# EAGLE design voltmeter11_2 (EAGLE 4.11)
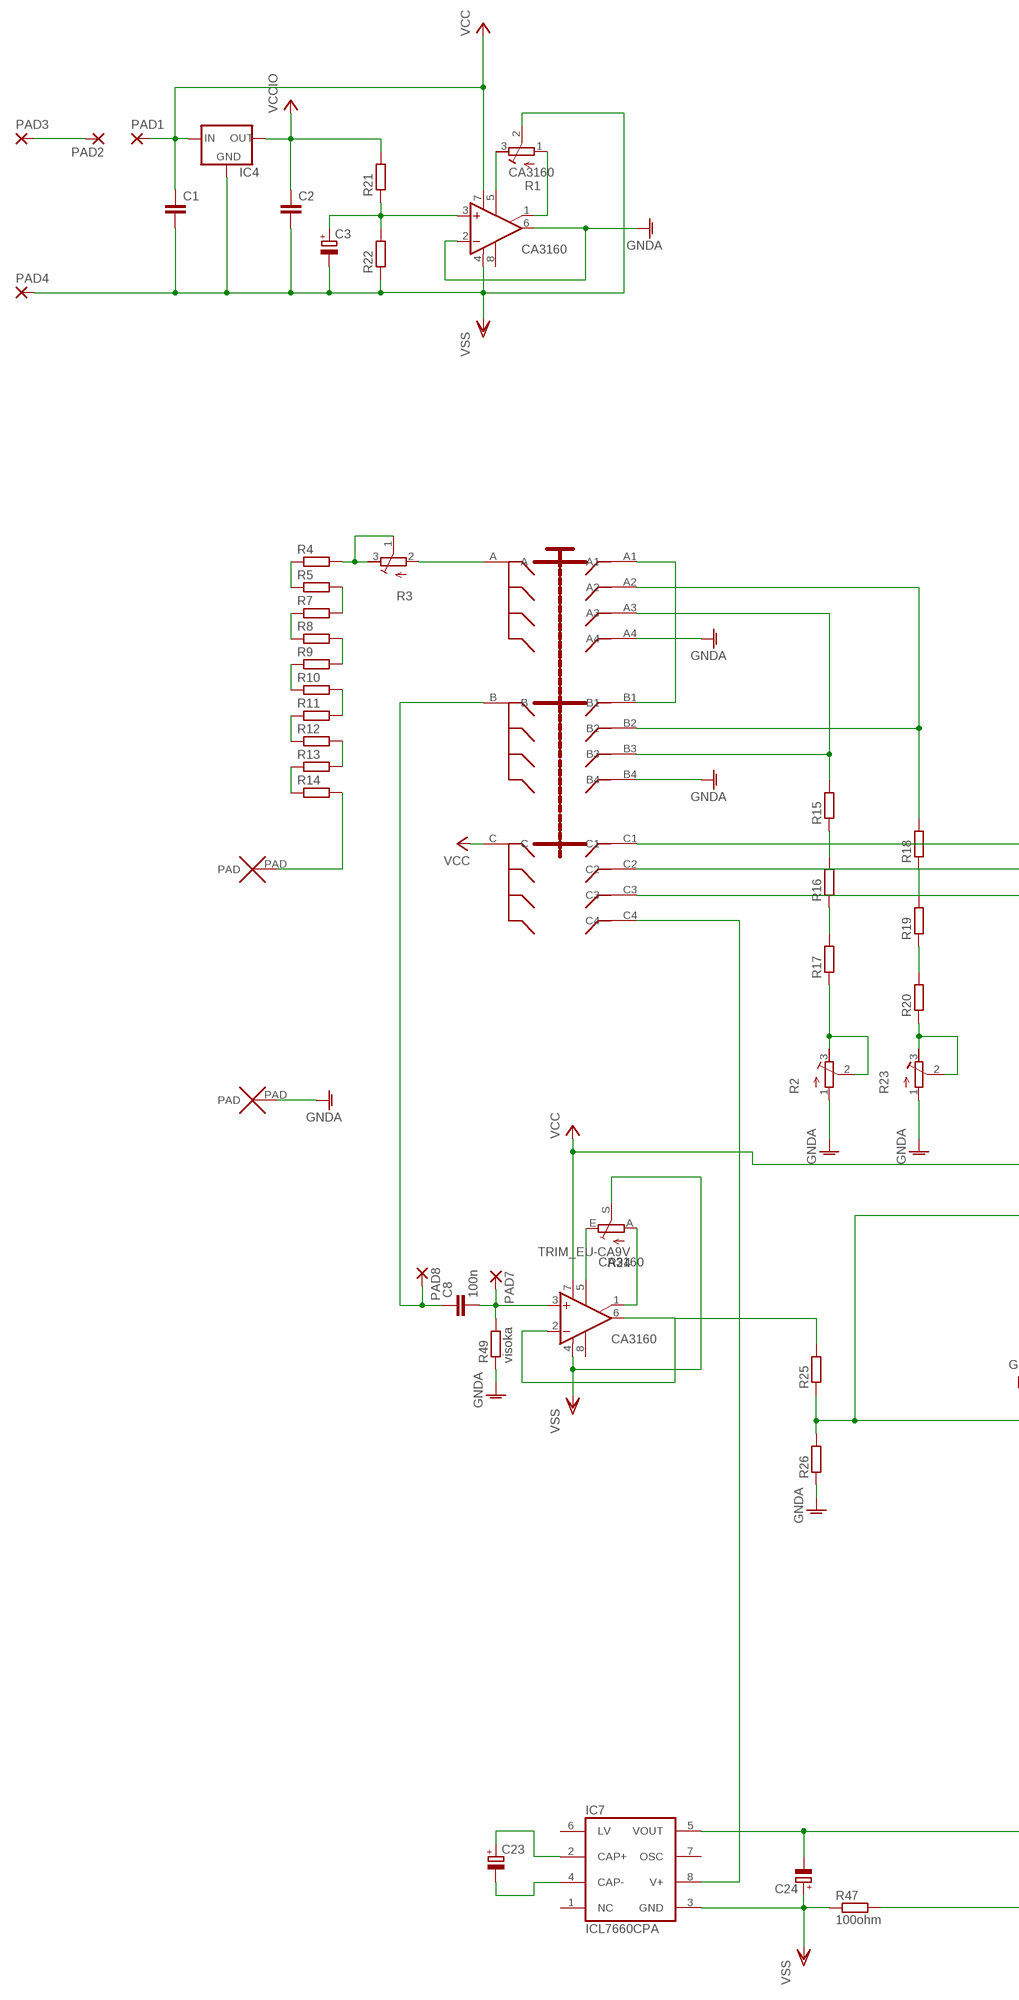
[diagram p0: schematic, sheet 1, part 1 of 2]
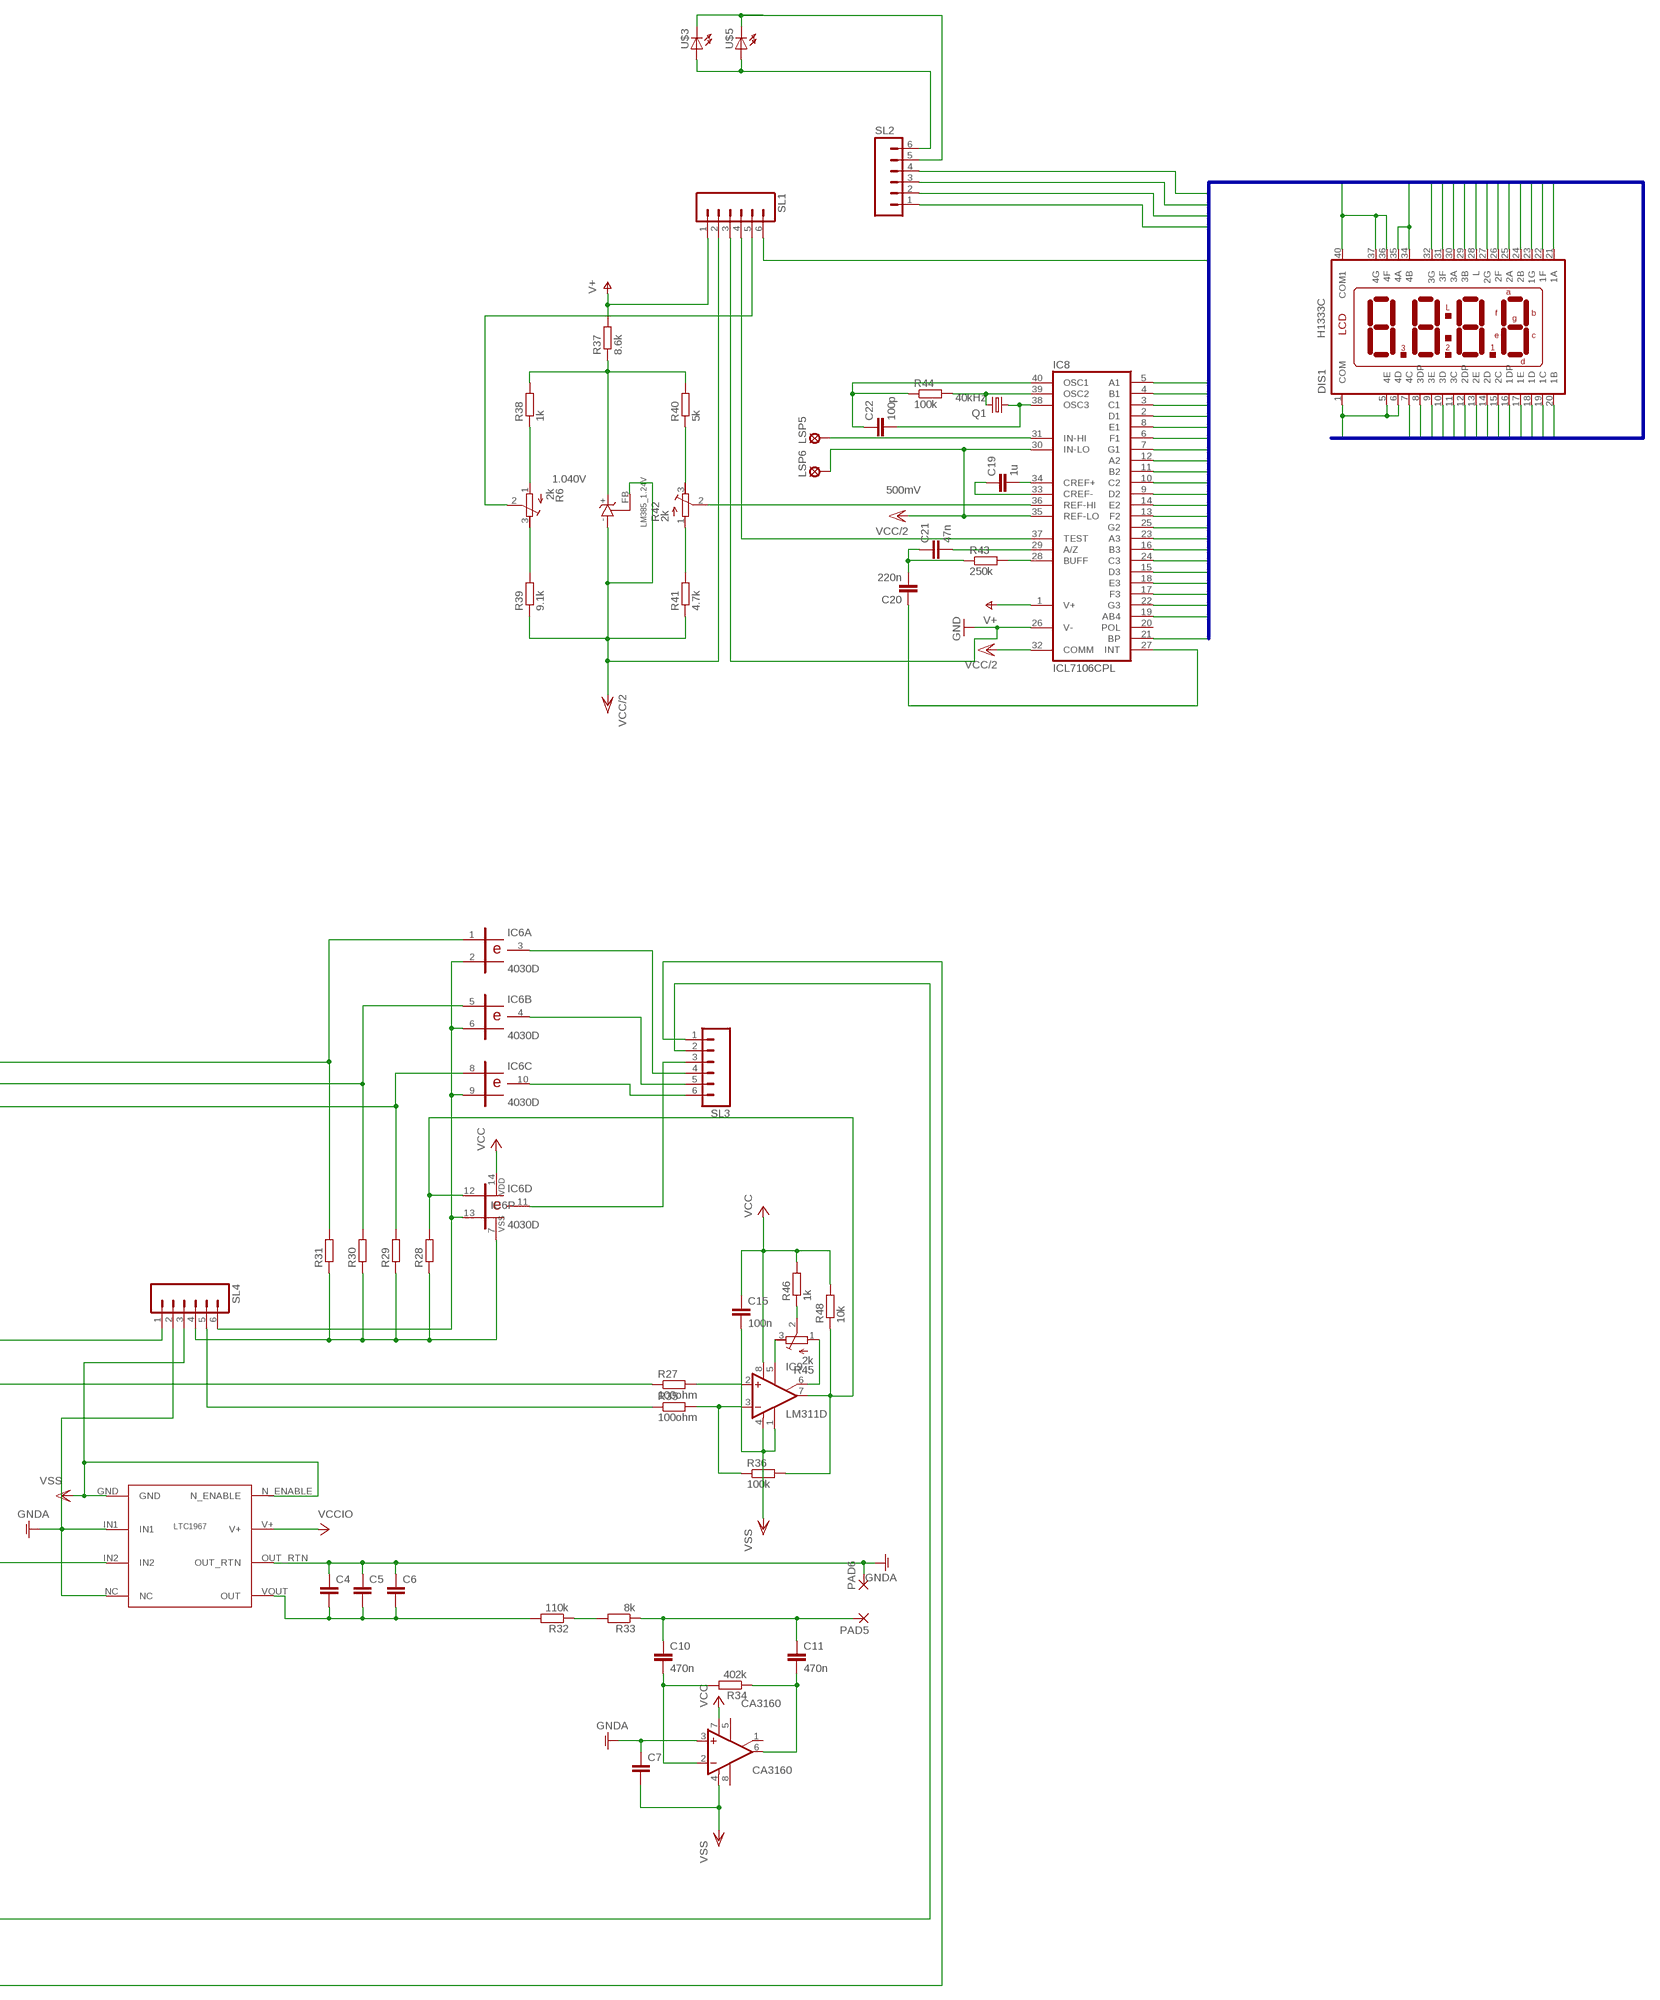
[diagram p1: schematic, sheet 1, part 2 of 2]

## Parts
C1  C-EUC1206  [C1206]
C2  C-EUC1206  [C1206]
C3  CPOL-EUB  [PANASONIC_B]
C4  C-EU050-050X075  [C050-050X075]
C5  C-EU050-050X075  [C050-050X075]
C6  C-EU050-035X075  [C050-035X075]
C7  C-EUC1206  [C1206]
C8  100n  C-EUC1206  [C1206]
C10  470n  C-EUC1206  [C1206]
C11  470n  C-EUC1206  [C1206]
C15  100n  C-EUC1206  [C1206]
C19  1u  C-EU050-050X075  [C050-050X075]
C20  220n  C-EU050-024X044  [C050-024X044]
C21  47n  C-EU050-024X044  [C050-024X044]
C22  100p  C-EUC1206  [C1206]
C23  CPOL-EUE5-8.5  [E5-8,5]
C24  CPOL-EUE5-8.5  [E5-8,5]
D2  LM385_1.24V  [LM385_1.24V]
DIS1  H1333C  [H1333C]
IC1  LTC1967  [LTC1967]
IC2  CA3160  [CA3160]
IC3  CA3160  [CA3160]
IC4  78XXL  [78XXL]
IC5  CA3160  [CA3160]
IC6  4030D  [SO14]
IC7  ICL7660CPA  [DIL08]
IC8  ICL7106CPL  [DIL40]
IC9  LM311D  [SO08]
LSP5  LSP10  [LSP10]
LSP6  LSP10  [LSP10]
PAD1  1,6/0,8  [1,6/0,8]
PAD2  1,6/0,8  [1,6/0,8]
PAD3  1,6/0,8  [1,6/0,8]
PAD4  1,6/0,8  [1,6/0,8]
PAD5  1,6/0,8  [1,6/0,8]
PAD6  1,6/0,8  [1,6/0,8]
PAD7  1,6/0,8  [1,6/0,8]
PAD8  1,6/0,8  [1,6/0,8]
Q1  40kHz  CRYTALTC26V  [TC26V]
R1  TRIMER  [C3203]
R2  TRIMER  [C3203]
R3  TRIMER406  [406]
R4  R-EU_R1206  [R1206]
R5  R-EU_R1206  [R1206]
R6  2k  TRIMER  [C3203]
R7  R-EU_R1206  [R1206]
R8  R-EU_R1206  [R1206]
R9  R-EU_R1206  [R1206]
R10  R-EU_R1206  [R1206]
R11  R-EU_R1206  [R1206]
R12  R-EU_R1206  [R1206]
R13  R-EU_R1206  [R1206]
R14  R-EU_R1206  [R1206]
R15  R-EU_R1206  [R1206]
R16  R-EU_R1206  [R1206]
R17  R-EU_R1206  [R1206]
R18  R-EU_R1206  [R1206]
R19  R-EU_R1206  [R1206]
R20  R-EU_R1206  [R1206]
R21  R-EU_R1206  [R1206]
R22  R-EU_R1206  [R1206]
R23  TRIMER  [C3203]
R24  TRIM_EU-CA9V  [CA9V]
R25  R-EU_R1206  [R1206]
R26  R-EU_R1206  [R1206]
R27  100ohm  R-EU_R1206  [R1206]
R28  R-EU_R1206  [R1206]
R29  R-EU_R1206  [R1206]
R30  R-EU_R1206  [R1206]
R31  R-EU_R1206  [R1206]
R32  110k  R-EU_R1206  [R1206]
R33  8k  R-EU_R1206  [R1206]
R34  402k  R-EU_R1206  [R1206]
R35  100ohm  R-EU_R1206  [R1206]
R36  100k  R-EU_R1206  [R1206]
R37  8.6k  R-EU_R1206  [R1206]
R38  1k  R-EU_R1206  [R1206]
R39  9.1k  R-EU_R1206  [R1206]
R40  5k  R-EU_R1206  [R1206]
R41  4.7k  R-EU_R1206  [R1206]
R42  2k  TRIMER  [C3203]
R43  250k  R-EU_R1206  [R1206]
R44  100k  R-EU_R1206  [R1206]
R45  2k  TRIMER  [C3203]
R46  1k  R-EU_R1206  [R1206]
R47  100ohm  R-EU_R1206  [R1206]
R48  10k  R-EU_R1206  [R1206]
R49  visoka  R-EU_R1206  [R1206]
S1  PREKLOPNIK_3NA4_HTE  [PREKLOPNIK_3NA4_HTE]
SL1  M06  [06P]
SL2  M06  [06P]
SL3  M06  [06P]
SL4  M06  [06P]
U$1  PAD  [PUSA]
U$2  PAD  [PUSA]
U$3  LEDB155  [Q62902-B155]
U$5  LEDB155  [Q62902-B155]

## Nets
1.040V: R6.2 SL1.5
1.040V1: R35.1 SL4.5
1DP: DIS1.16(1DP) SL2.1
2DP: DIS1.12(2DP) SL2.2
2V_: IC6.3(A:O) SL3.4
2VXOR: IC6.1(A:I0) R31.2 S1.C1
3DP: DIS1.8(3DP) SL2.3
20V: R18.2 S1.A2 S1.B2
20V_: IC6.4(B:O) SL3.5
20VXOR: IC6.5(B:I0) R30.2 S1.C2
200V: R15.2 S1.A3 S1.B3
200V_: IC6.10(C:O) SL3.6
200VXOR: IC6.8(C:I0) R29.2 S1.C3
A1: DIS1.21(1A) IC8.5(A1)
A2: DIS1.25(2A) IC8.12(A2)
A3: DIS1.30(3A) IC8.23(A3)
AB4: DIS1.7(4C) DIS1.34(4B) DIS1.35(4A) IC8.19(AB4)
B1: DIS1.20(1B) IC8.4(B1)
B2: DIS1.24(2B) IC8.11(B2)
B3: DIS1.29(3B) IC8.16(B3)
BP: DIS1.1(COM) DIS1.5(4E) DIS1.6(4D) DIS1.36(4F) DIS1.37(4G) DIS1.40(COM1) IC8.21(BP) SL1.6
BPXOR: IC6.2(A:I1) IC6.6(B:I1) IC6.9(C:I1) IC6.13(D:I1) SL4.6
C1: DIS1.19(1C) IC8.3(C1)
C2: DIS1.15(2C) IC8.10(C2)
C3: DIS1.11(3C) IC8.24(C3)
CLIP: DIS1.28(L) SL2.4
CLIP1: IC6.12(D:I0) IC9.7(OUT) R28.2 R36.2 R48.1
CLIP_: IC6.11(D:O) SL3.3
D1: DIS1.18(1D) IC8.2(D1)
D2: DIS1.14(2D) IC8.9(D2)
D3: DIS1.10(3D) IC8.15(D3)
DIG_GND: IC8.37(TEST) SL1.4
DIGGND: IC6.7(P:VSS) R28.1 R29.1 R30.1 R31.1 SL4.4
E1: DIS1.17(1E) IC8.8(E1)
E2: DIS1.13(2E) IC8.14(E2)
E3: DIS1.9(3E) IC8.18(E3)
F1: DIS1.22(1F) IC8.6(F1)
F2: DIS1.26(2F) IC8.13(F2)
F3: DIS1.31(3F) IC8.17(F3)
G1: DIS1.23(1G) IC8.7(G1)
G2: DIS1.27(2G) IC8.25(G2)
G3: DIS1.32(3G) IC8.22(G3)
GND: IC8.26(V-) SL1.3
GNDA: C4.1 C5.1 C6.1 C7.1 IC1.IN1 IC1.NC IC1.OUT_RTN IC2.2(-IN) IC2.6(OUT) IC5.3(+IN) PAD6.1(P) R2.1 R23.1 R26.1 R49.1 S1.A4 S1.B4 SL4.2 U$2.PAD
LED+: SL2.6 U$3.A U$5.A
LED+1: R47.2 SL3.1
LED-: SL2.5 U$3.K(C) U$5.K(C)
LED-1: C24.- IC7.5(VOUT) SL3.2
N$3: R3.2 S1.A
N$4: R4.1 R5.1
N$5: R5.2 R7.2
N$6: R7.1 R8.1
N$7: R8.2 R9.2
N$8: R9.1 R10.1
N$9: C19.2 IC8.34(CREF+)
N$10: R10.2 R11.2
N$11: R11.1 R12.1
N$12: R12.2 R13.2
N$13: R13.1 R14.1
N$14: R14.2 U$1.PAD
N$15: S1.A1 S1.B1
N$16: C3.+ IC2.3(+IN) R21.1 R22.2
N$17: IC1.IN2 R25.1 R26.2 R27.1
N$18: C8.1 PAD8.1(P) S1.B
N$19: C23.+ IC7.2(CAP+)
N$20: R3.1 R3.3 R4.2
N$21: PAD2.1(P) PAD3.1(P)
N$22: R15.1 R16.2
N$23: R18.1 R19.2
N$24: R16.1 R17.2
N$25: R19.1 R20.2
N$26: R2.2 R2.3 R17.1
N$27: IC3.2(-IN) IC3.6(OUT) R25.2
N$28: R20.1 R23.2 R23.3
N$29: IC2.5(OFFSET2) R1.3
N$30: IC2.1(OFFSET1) R1.1
N$31: IC3.5(OFFSET2) R24.E
N$32: IC3.1(OFFSET1) R24.A
N$33: C8.2 IC3.3(+IN) PAD7.1(P) R49.2
N$34: IC9.3(-IN) R35.2 R36.1
N$35: C23.- IC7.4(CAP-)
N$36: R32.1 R33.2
N$37: C10.1 C11.1 PAD5.1(P) R33.1
N$39: C4.2 C5.2 C6.2 IC1.VOUT(OUT) R32.2
N$40: IC9.2(+IN) R27.2
N$41: C10.2 IC5.2(-IN) R34.2
N$42: C11.2 IC5.6(OUT) R34.1
N$48: IC9.5(ON) R45.3
N$49: IC9.6(ON/STR) R45.1
N$50: R45.2 R46.1
N$58: D2.+ R37.1 R38.2 R40.2
N$59: IC8.36(REF-HI) R42.2
N$60: R6.1 R38.1
N$61: R40.1 R42.3
N$62: R6.3 R39.2
N$63: R41.2 R42.1
N$64: C19.1 IC8.33(CREF-)
N$65: IC8.31(IN-HI) LSP5.MP
N$67: C21.2 IC8.29(A/Z)
N$68: IC8.28(BUFF) R43.2
N$70: C20.2 C21.1 R43.1
N$71: C20.1 IC8.27(INT)
N$72: C22.2 IC8.38(OSC3) Q1.1
N$73: C22.1 IC8.40(OSC1) R44.1
N$75: IC8.39(OSC2) Q1.2 R44.2
N$84: IC7.8(V+) S1.C4
VBATT: IC8.1(V+) R37.2 SL1.1 ; supply symbol labelled V+
VCC: C1.1 C15.1 IC2.7(+V) IC3.7(+V) IC4.IN IC5.7(+V) IC6.14(P:VDD) IC9.8(V+) PAD1.1(P) R46.2 R48.2 S1.C SL4.1
VCC/2_+_50MV: D2.- D2.FB IC8.30(IN-LO) IC8.32(COMM) IC8.35(REF-LO) LSP6.MP R39.1 R41.1 SL1.2 ; supply symbol labelled VCC/2
VCCIO: C2.1 IC1.V+ IC4.OUT R21.2
VSS: C1.2 C2.2 C3.- C7.2 C15.2 C24.+ IC1.GND IC1.N_ENABLE IC2.4(V-) IC3.4(V-) IC4.GND IC5.4(V-) IC7.3(GND) IC9.1(GND) IC9.4(V-) PAD4.1(P) R1.2 R22.1 R24.S R47.1 SL4.3
Unconnected: IC2.8(STROBE) IC3.8(STROBE) IC5.1(OFFSET1) IC5.5(OFFSET2) IC5.8(STROBE) IC7.1(NC) IC7.6(LV) IC7.7(OSC) IC8.20(POL)

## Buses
B$1

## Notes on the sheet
- 1.040V
- 500mV

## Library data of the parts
C1 C2 C4-C8 C10 C11 C15 C19-C22 = rcl:C-EU: CAPACITOR, European symbol
C3 C23 C24 = rcl:CPOL-EU: POLARIZED CAPACITOR, European symbol
D2 = voltmeter:LM385_1.24V
DIS1 = display-lcd:H1333C: LCD DISPLAY 4-character 7 segment
IC1 = voltmeter:LTC1967
IC2 IC3 IC5 = voltmeter:CA3160
IC4 = v-reg:78XXL: VOLTAGE REGULATOR
IC6 = 40xx:4030: Quad XOR
IC7 = maxim:ICL7660CPA: VOLTAGE CONVERTER
IC8 = maxim:ICL7106CPL: LCD DRIVER
IC9 = linear:LM311: COMPARATOR
LSP5 LSP6 = solpad:LSP10: SOLDER PAD
PAD1-PAD8 = wirepad:1,6/0,8: THROUGH-HOLE PAD
Q1 = crystal:CRYTAL: CRYSTAL
R1-R3 R6 R23 R42 R45 = voltmeter:TRIMER
R4 R5 R7-R22 R25-R41 R43 R44 R46-R49 = rcl:R-EU_: RESISTOR, European symbol
R24 = pot:TRIM_EU-: POTENTIOMETER
S1 = voltmeter:PREKLOPNIK_3NA4_HTE
SL1-SL4 = con-amp-quick:M06: AMP QUICK CONNECTOR
U$1 U$2 = voltmeter:PAD
U$3 U$5 = led:LED: LED

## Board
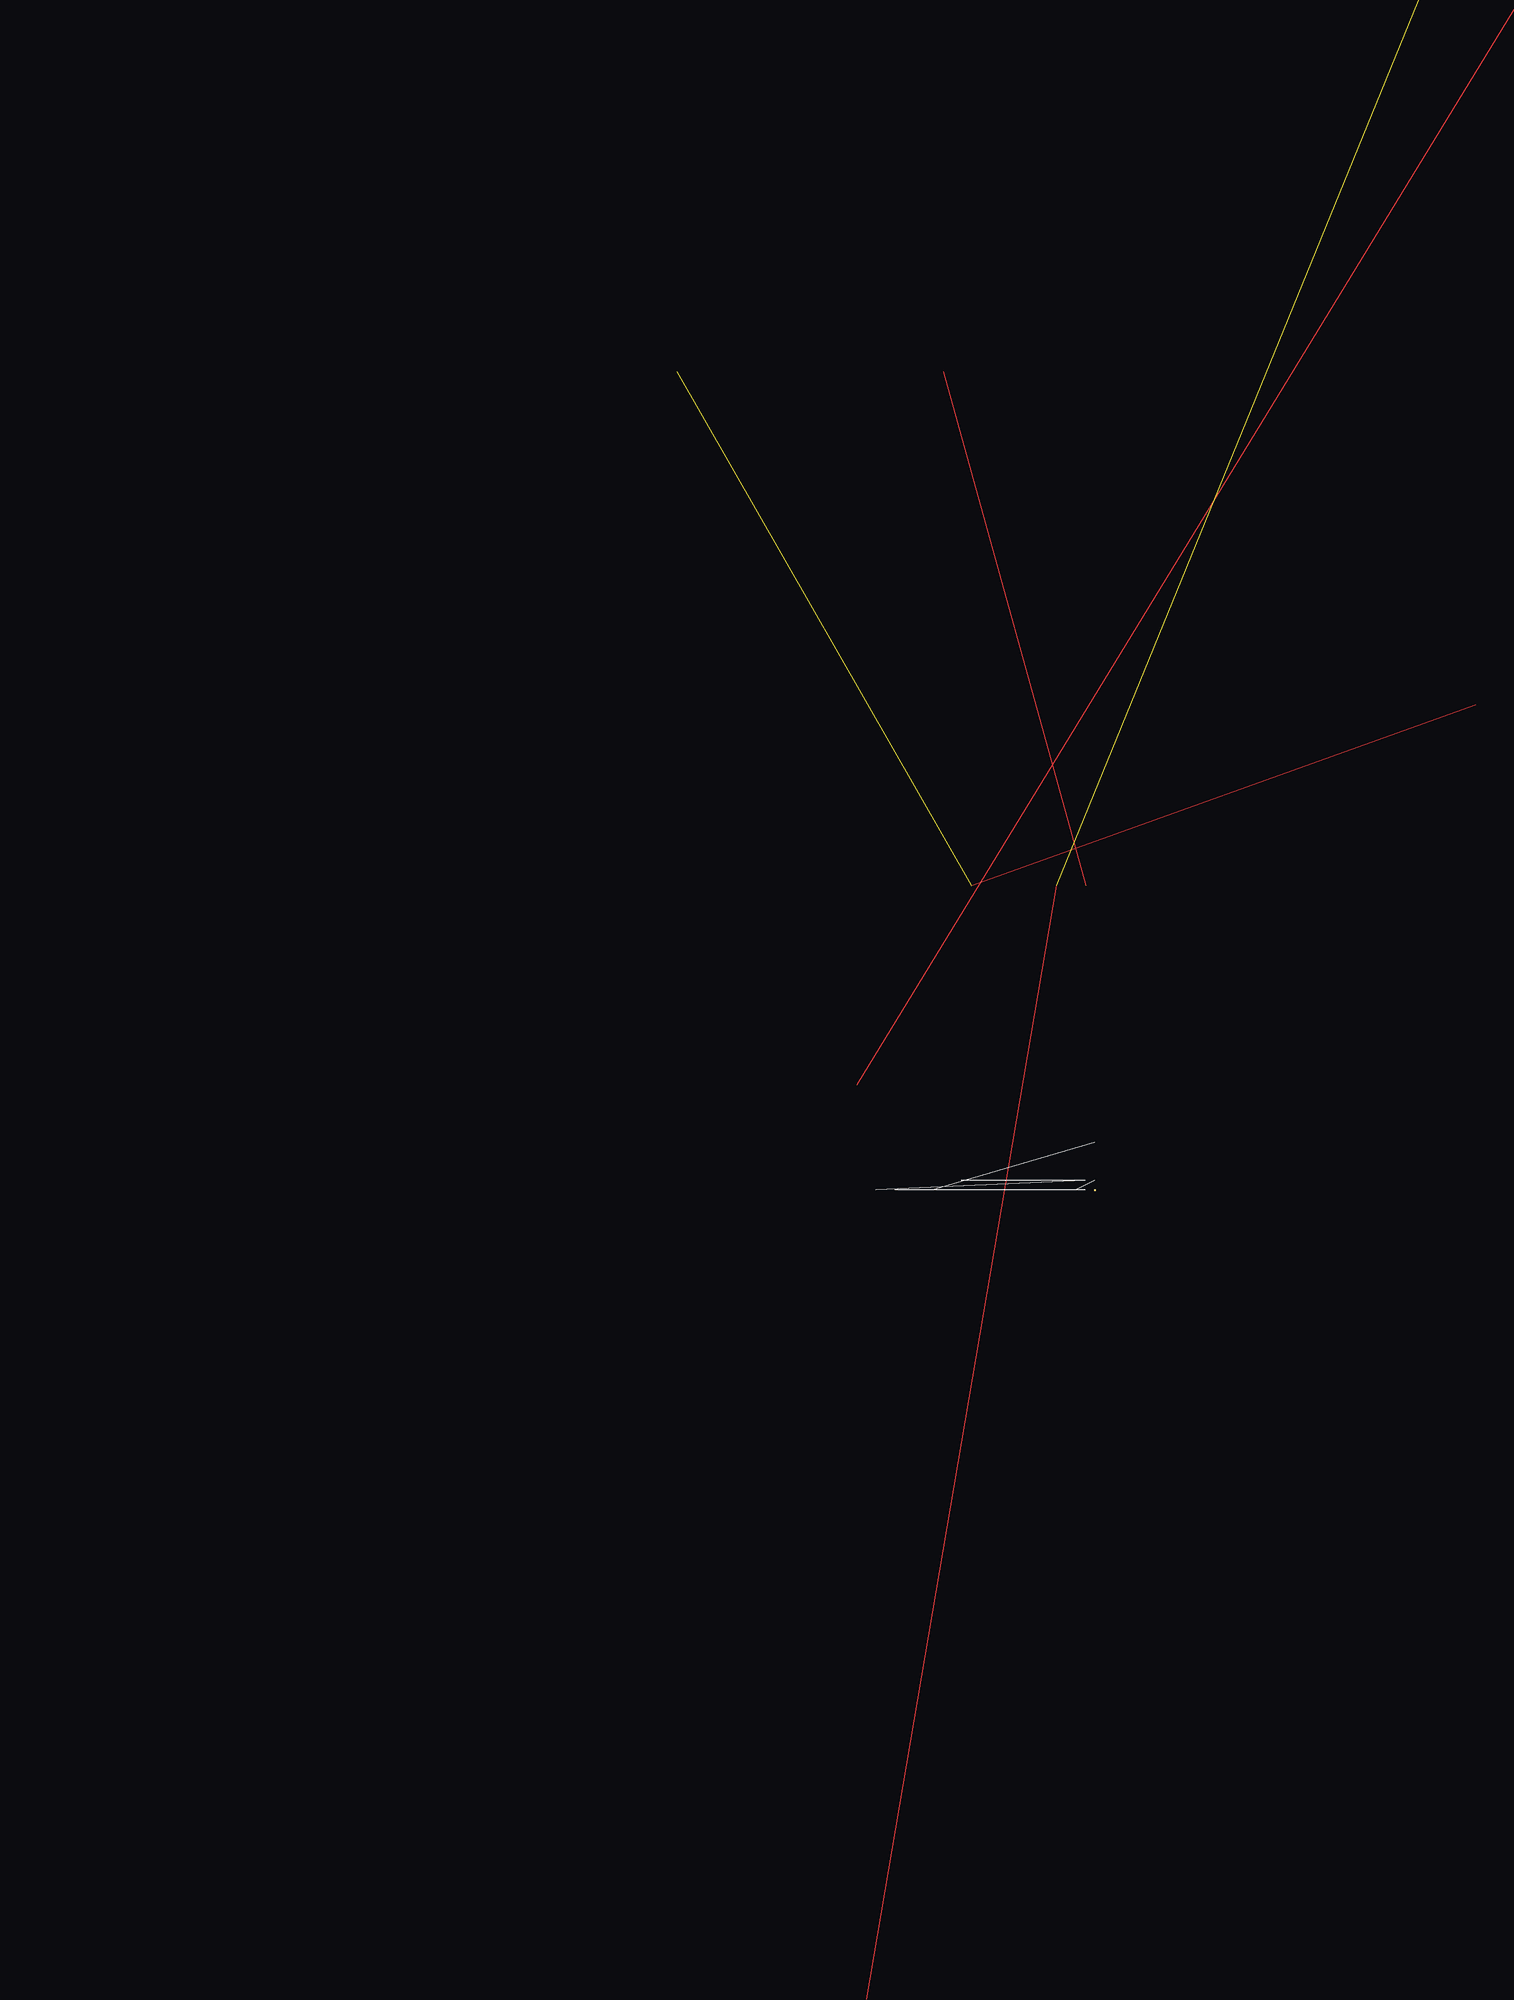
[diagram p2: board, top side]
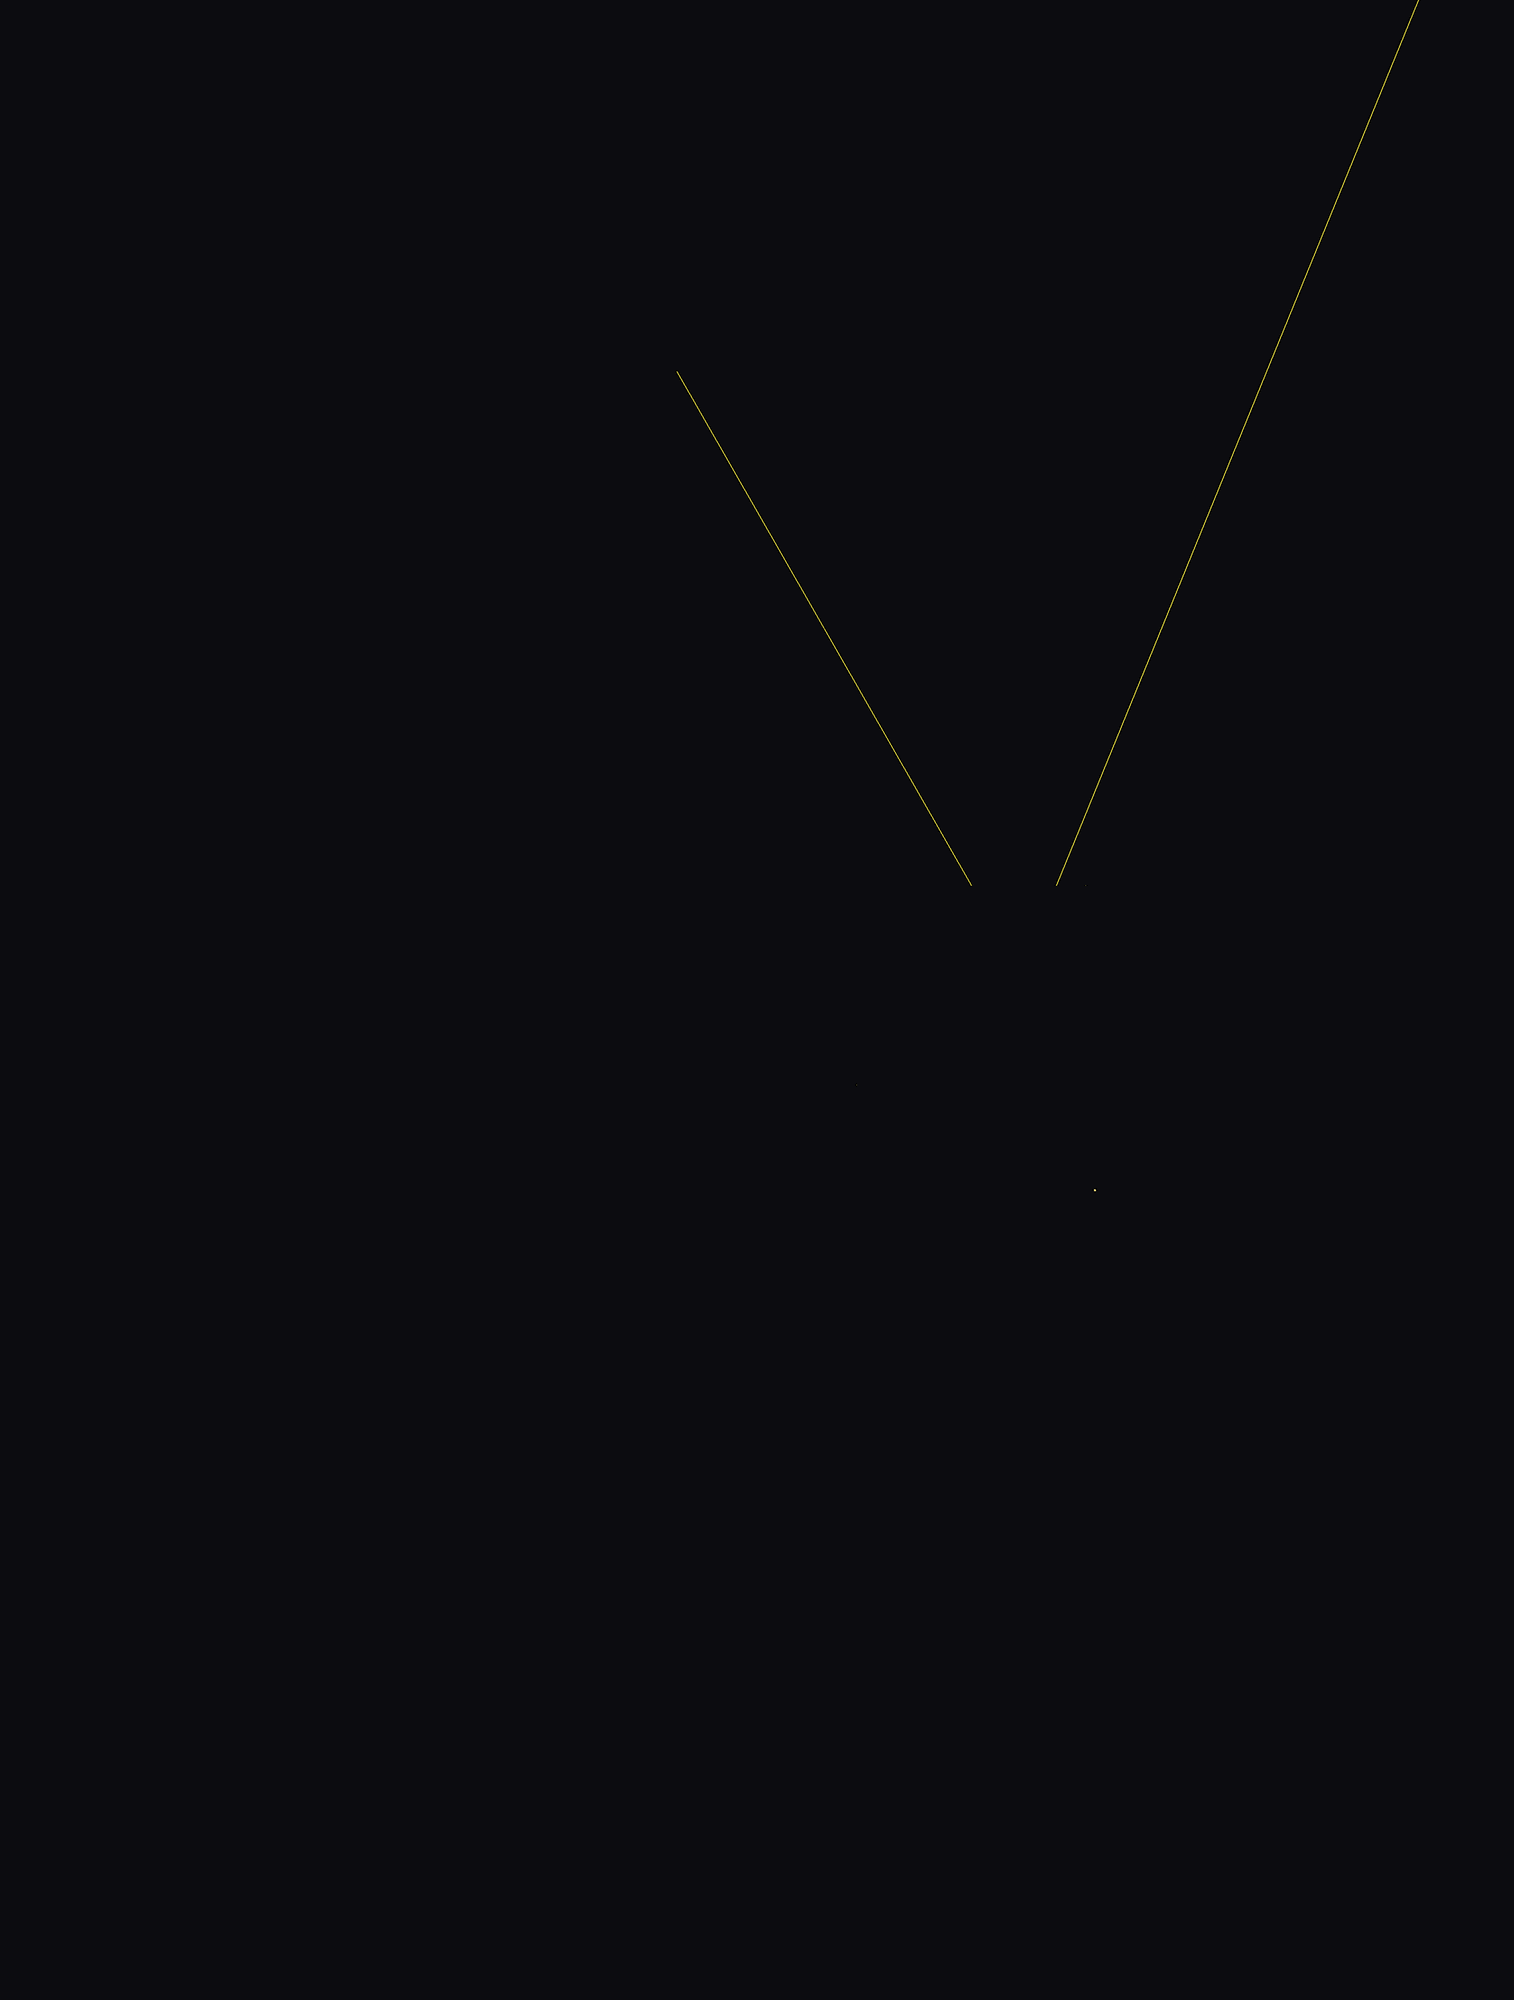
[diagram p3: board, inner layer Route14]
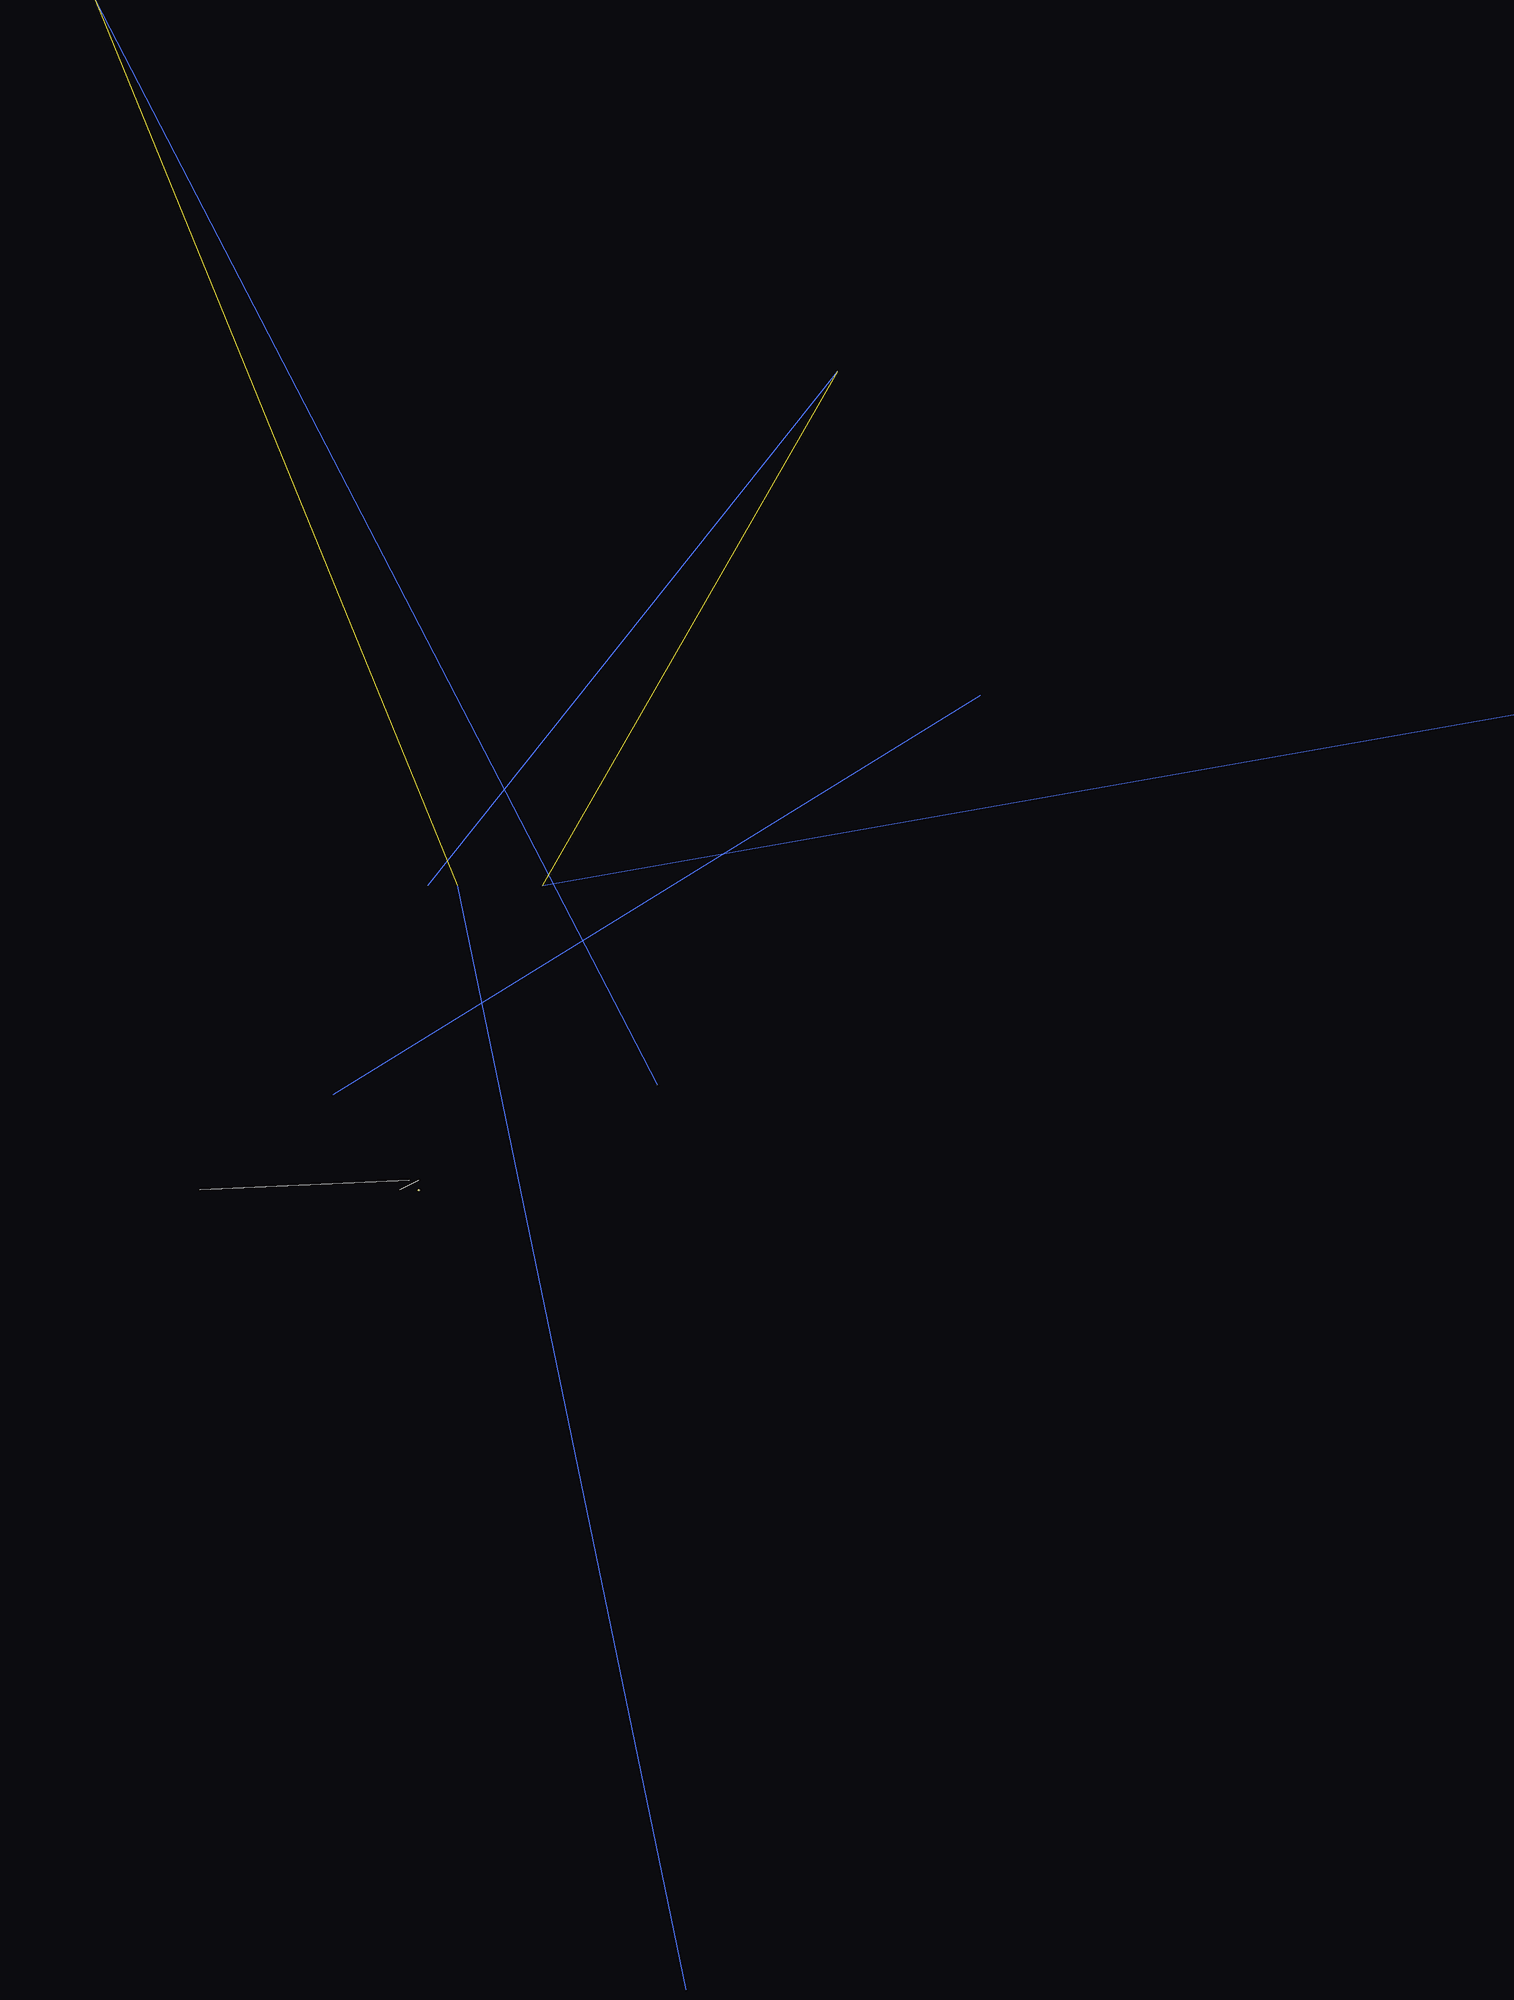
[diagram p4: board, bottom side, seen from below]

Size 165.67 x 104.97 mm. Coordinates in mm from the lower left corner, seen from the top.
Outline: 64 segments
Outline: circle at 30.16,94.42 radius 2.54
Outline: circle at 6.67,92.39 radius 2.54
Outline: circle at 30.16,10.35 radius 2.54
Outline: circle at 6.67,12.38 radius 2.54
Outline: circle at 156.27,100.84 radius 2.54
Outline: circle at 163.13,21.27 radius 2.54
Outline: circle at 89.98,100.84 radius 2.54
Outline: circle at 83.12,21.27 radius 2.54
Copper layers (1+14*16): Top 0.035mm / dielectric 0.75mm / Route14 0.035mm / dielectric 0.75mm / Bottom 0.035mm
Design rules "default": minimum track width 10mil, minimum drill 24mil, track to track 8mil, track to pad 8mil, pad to pad 8mil, via to via 8mil, smd to smd 8mil, copper to edge 40mil, drill to drill 8mil, minimum pad ring 15mil, minimum via ring 15mil, stop-mask expansion 4mil, vias tented up to drill 0mil, thermal gap 10mil

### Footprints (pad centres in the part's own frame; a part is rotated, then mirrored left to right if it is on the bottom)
C1206 = smd 1.6 x 1.8: 1 -1.4,0; 2 1.4,0
PANASONIC_B = smd 2.2 x 1.4: + 1.6,0; - -1.6,0
C050-050X075 = drill 0.813 octagon: 1 -2.54,0; 2 2.54,0
C050-035X075 = drill 0.813 octagon: 1 -2.54,0; 2 2.54,0
C050-024X044 = drill 0.813 octagon: 1 -2.54,0; 2 2.54,0
E5-8,5 = drill 1.016 pad 2.54 round: + -2.54,0 | drill 1.016 pad 2.54 octagon: - 2.54,0
LM385_1.24V = drill 0.813 octagon: + 0,1.905; - 1.27,0; FB -1.27,0
H1333C = drill 0.813 long: 1 -24.13,-16.51; 2 -21.59,-16.51; 3 -19.05,-16.51; 4 -16.51,-16.51; 5 -13.97,-16.51; 6 -11.43,-16.51; 7 -8.89,-16.51; 8 -6.35,-16.51; 9 -3.81,-16.51; 10 -1.27,-16.51; 11 1.27,-16.51; 12 3.81,-16.51; 13 6.35,-16.51; 14 8.89,-16.51; 15 11.43,-16.51; 16 13.97,-16.51; 17 16.51,-16.51; 18 19.05,-16.51; 19 21.59,-16.51; 20 24.13,-16.51; 21 24.13,16.51; 22 21.59,16.51; 23 19.05,16.51; 24 16.51,16.51; 25 13.97,16.51; 26 11.43,16.51; 27 8.89,16.51; 28 6.35,16.51; 29 3.81,16.51; 30 1.27,16.51; 31 -1.27,16.51; 32 -3.81,16.51; 33 -6.35,16.51; 34 -8.89,16.51; 35 -11.43,16.51; 36 -13.97,16.51; 37 -16.51,16.51; 38 -19.05,16.51; 39 -21.59,16.51; 40 -24.13,16.51
LTC1967 = smd 0.813 x 0.406: GND -10.604,6.731; IN1 -10.604,6.032; IN2 -10.604,5.334; N_ENABLE -6.287,6.731; NC -10.604,4.636; OUT_RTN -6.287,5.334; V+ -6.287,6.032; VOUT -6.287,4.636
CA3160 = drill 0.813 long: 1 -3.81,-3.81; 2 -1.27,-3.81; 3 1.27,-3.81; 4 3.81,-3.81; 5 3.81,3.81; 6 1.27,3.81; 7 -1.27,3.81; 8 -3.81,3.81
78XXL = drill 1.016 long: GND 0,-3.81; IN -2.54,-3.81; OUT 2.54,-3.81 | hole 3.302: 0,11.176
SO14 = smd 0.66 x 2.032: 1 -3.81,-3.073; 2 -2.54,-3.073; 3 -1.27,-3.073; 4 0,-3.073; 5 1.27,-3.073; 6 2.54,-3.073; 7 3.81,-3.073; 8 3.81,3.073; 9 2.54,3.073; 10 1.27,3.073; 11 0,3.073; 12 -1.27,3.073; 13 -2.54,3.073; 14 -3.81,3.073
DIL08 = drill 0.813 long: 1 -3.81,-3.81; 2 -1.27,-3.81; 3 1.27,-3.81; 4 3.81,-3.81; 5 3.81,3.81; 6 1.27,3.81; 7 -1.27,3.81; 8 -3.81,3.81
DIL40 = drill 0.813 long: 1 -24.13,-7.62; 2 -21.59,-7.62; 3 -19.05,-7.62; 4 -16.51,-7.62; 5 -13.97,-7.62; 6 -11.43,-7.62; 7 -8.89,-7.62; 8 -6.35,-7.62; 9 -3.81,-7.62; 10 -1.27,-7.62; 11 1.27,-7.62; 12 3.81,-7.62; 13 6.35,-7.62; 14 8.89,-7.62; 15 11.43,-7.62; 16 13.97,-7.62; 17 16.51,-7.62; 18 19.05,-7.62; 19 21.59,-7.62; 20 24.13,-7.62; 21 24.13,7.62; 22 21.59,7.62; 23 19.05,7.62; 24 16.51,7.62; 25 13.97,7.62; 26 11.43,7.62; 27 8.89,7.62; 28 6.35,7.62; 29 3.81,7.62; 30 1.27,7.62; 31 -1.27,7.62; 32 -3.81,7.62; 33 -6.35,7.62; 34 -8.89,7.62; 35 -11.43,7.62; 36 -13.97,7.62; 37 -16.51,7.62; 38 -19.05,7.62; 39 -21.59,7.62; 40 -24.13,7.62
SO08 = smd 0.6 x 2.2: 1 -1.905,-2.6; 2 -0.635,-2.6; 3 0.635,-2.6; 4 1.905,-2.6; 5 1.905,2.6; 6 0.635,2.6; 7 -0.635,2.6; 8 -1.905,2.6
LSP10 = drill 1.016 pad 2.159 octagon: MP 0,0
1,6/0,8 = drill 0.813 pad 1.6 octagon: 1 0,0
TC26V = drill 0.813 round: 1 -1.27,0; 2 1.27,0
C3203 = smd 0.813 x 1.676: 1 -0.953,-3.683; 3 0.889,-3.683 | smd 1.93 x 0.965: 2 0,0
406 = drill 0.813 round: 1 -2.54,-2.54; 2 0,0; 3 2.54,-2.54
R1206 = smd 1.6 x 1.803: 1 -1.422,0; 2 1.422,0
CA9V = drill 1.321 long: A -2.54,-5.08; E 2.54,-5.08; S 0,5.08
PREKLOPNIK_3NA4_HTE = drill 0.813 round: A -4.318,1.143; A1 -6.54,0; A2 -5.652,3.302; A3 -3.239,5.652; A4 0,6.54; B 3.239,3.175; B1 3.239,5.652; B2 5.652,3.302; B3 6.54,0; B4 5.652,-3.302; C 1.143,-4.318; C1 3.302,-5.652; C2 0,-6.54; C3 -3.302,-5.652; C4 -5.652,-3.302
06P = drill 0.914 long: 1 -6.35,0; 2 -3.81,0; 3 -1.27,0; 4 1.27,0; 5 3.81,0; 6 6.35,0
PUSA = drill 3.81 round: PAD 0,0
Q62902-B155 = drill 0.813 long: A 7.62,-1.27; K 7.62,1.27 | hole 0.813: 0,0

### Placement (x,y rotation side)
C1  90.17,69.34 0 bottom
C2  85.47,70.23 90 bottom
C3  81.28,74.68 90 bottom
C4  138.68,88.77 90 top
C5  133.22,88.71 90 top
C6  128.52,88.71 90 top
C7  148.86,82.78 0 top
C8  147.17,77.42 90 bottom
C10  143.26,98.42 0 top
C11  143.26,101.73 0 top
C15  164.59,40.51 90 top
C19  34.86,60.26 90 top
C20  32.32,43.75 0 bottom
C21  32.32,48.83 180 bottom
C22  31.69,72.33 270 top
C23  160.85,79.57 180 top
C24  160.78,94.17 180 top
D2  28.51,73.6 90 top
DIS1  30.42,52.64 90 top
IC1  129.41,78.68 180 top
IC2  89.41,83.25 270 top
IC3  145.16,63.5 180 top
IC4  86.49,60.26 180 top
IC5  147.19,89.79 0 top
IC6  130.75,29.53 90 top
IC7  160.85,86.8 90 top
IC8  46.93,52.64 270 bottom
IC9  159.96,41.72 180 top
LSP5  34.23,52.01 90 top
LSP6  34.23,55.18 90 top
PAD1  94.74,63.88 270 top
PAD2  97.85,63.82 270 top
PAD3  97.85,69.79 270 top
PAD4  94.74,69.79 270 top
PAD5  137.6,101.73 0 top
PAD6  125.22,101.47 0 top
PAD7  150.17,76.93 90 top
PAD8  143.98,76.1 90 top
Q1  35.5,72.96 90 top
R1  95,73.09 180 top
R2  92.77,21.65 270 bottom
R3  85.28,36.51 90 top
R4  91.82,37.66 90 top
R5  96.46,37.66 90 top
R6  24.7,55.82 270 bottom
R7  101.47,37.66 90 top
R8  101.47,29.02 270 top
R9  96.33,29.02 270 top
R10  91.25,29.02 270 top
R11  91.25,20.19 90 top
R12  96.27,20.19 90 top
R13  101.66,20.19 90 top
R14  103.25,13.46 270 top
R15  96.27,35.5 180 bottom
R16  96.33,31.12 0 bottom
R17  96.33,27.18 180 bottom
R18  103.19,35.5 0 bottom
R19  103.19,31.18 180 bottom
R20  103.19,26.54 0 bottom
R21  85.47,70.29 270 top
R22  91.31,73.03 90 top
R23  106.11,21.78 90 bottom
R24  145.35,48.77 180 top
R25  149.1,72.11 270 top
R26  139.95,79.25 0 top
R27  159.19,52.9 0 top
R28  120.33,28.32 180 bottom
R29  132.97,37.91 180 top
R30  145.1,31.69 180 top
R31  145.1,25.65 180 top
R32  129.98,96.2 180 top
R33  135.83,96.2 180 top
R34  148.46,99.89 270 top
R35  156.08,48.26 0 top
R36  155.45,42.55 270 top
R37  26.61,64.07 180 bottom
R38  26.61,60.9 0 bottom
R39  23.43,72.33 270 bottom
R40  26.61,67.25 0 bottom
R41  20.26,72.33 270 bottom
R42  36.13,66.61 90 bottom
R43  32.96,46.29 0 top
R44  32.96,77.41 0 top
R45  158.69,32.32 180 top
R46  162.94,33.72 90 top
R47  164.02,97.54 0 bottom
R48  159.25,27.62 0 top
R49  141.4,81.11 270 bottom
S1  123.06,64.26 0 top
SL1  63.44,15.81 90 top
SL2  63.44,31.05 270 top
SL3  114.49,94.23 0 top
SL4  99.38,94.23 0 top
U$1  93.79,7.87 0 top
U$2  152.34,7.94 0 top
U$3  -3.24,34.23 0 top
U$5  -3.24,71.06 0 top

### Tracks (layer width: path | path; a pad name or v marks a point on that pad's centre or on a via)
1.040V  (via drill 0.81)
  Top 0.406: v22.8,17.72 v22.8,52.64 | v43.82,17.59 58.99,17.59 60.96,19.62 SL1.5
  Bottom 0.406: R6.2 23.43,55.82 22.8,55.18 v22.8,52.64 | v22.8,17.72 24.32,18.86 37.91,18.86 39.18,17.59 v43.82,17.59
1.040V1  (via drill 0.81)
  Top 0.406: v160.58,76.81 160.58,73.4 165.71,73.41 165.73,55.63 159.19,55.69 159.19,50.8 154.69,50.8 154.69,48.26 R35.1
  Bottom 0.406: SL4.5 103.19,89.53 115.76,89.53 115.76,83.38 135.7,83.38 135.7,81.1 143.23,81.1 144.51,81.09 150.79,81.09 152.53,81.09 152.53,79.61 152.53,76.81 154.93,76.81 v160.58,76.81
1DP
  Top 0.406: DIS1.16 50.1,66.61 51.37,65.34 58.36,65.34 58.36,37.4 SL2.1
2DP
  Top 0.406: DIS1.12 48.83,56.45 52.01,53.28 52.01,34.86 SL2.2
2V_  (via drill 0.81)
  Top 0.406: IC6.3 138.49,28.26 v138.49,27.05 | v114.68,41.47 113.73,41.47 105.54,49.47 v105.54,51.56 | v105.47,60.26 105.47,72.77 115.82,83.12 115.82,94.3 SL3.4
  Bottom 0.406: v138.49,27.05 138.49,37.21 136.91,38.8 123.25,38.8 120.59,41.47 v114.68,41.47 | v105.54,51.56 105.54,60.2 v105.47,60.26
2VXOR  (via drill 0.81)
  Top 0.406: v128.4,50.64 137.86,50.64 137.86,40.77 153.48,40.77 153.48,19.81 141.22,19.81 | 141.22,19.81 133.79,19.81 133.79,25.72 IC6.1 133.92,25.72 133.98,25.65 | R31.2 142.75,25.65 141.22,24.13 141.22,19.81
  Bottom 0.406: S1.C1 128.4,56.58 v128.4,50.64
3DP
  Top 0.406: DIS1.8 50.74,46.29 50.74,32.32 SL2.3
20V
  Bottom 0.406: 101.77,35.52 101.73,35.56 | 101.77,35.52 R18.2 | 101.77,35.52 101.73,37.4 112.65,37.4 112.65,67.56 S1.A2 117.47,67.63 121.48,67.63 121.92,67.18 121.92,63.25 123.25,61.91 125.54,61.91 128.84,58.61 129.57,57.92 130.58,58.93 131.95,60.81 131.95,62.47 131.89,62.54 131.89,65.6 129.92,67.56 S1.B2
20V_  (via drill 0.81)
  Top 0.406: IC6.4 140.08,29.53 v140.08,30.8 | v114.87,44.39 113.66,44.39 113.03,45.02 107.82,49.98 v107.82,51.56 | v107.89,60.39 107.89,72.77 118.36,82.93 118.36,94.17 SL3.5
  Bottom 0.406: v140.08,30.8 140.08,38.86 138.81,40.51 128.4,40.51 124.33,44.32 v114.87,44.39 | v107.82,51.56 107.89,51.75 v107.89,60.39
20VXOR  (via drill 0.81)
  Top 0.406: v123.13,48.55 126.75,44.93 132.97,44.93 132.97,36.07 131.76,34.86 131.76,31.43 132.4,30.8 133.67,30.8 | 133.67,30.8 IC6.5 | 133.67,30.8 136.65,30.8 138.49,32.89 141.8,32.89 142.56,31.69 R30.2 | 133.67,30.8 133.6,30.86
  Bottom 0.406: S1.C2 123.13,57.66 v123.13,48.55
200V
  Bottom 0.406: R15.2 97.69,35.46 97.66,35.43 97.79,35.43 97.79,39.88 111.57,39.88 111.57,69.91 S1.A3 119.82,76.77 124.71,76.77 124.71,65.53 125.29,64.96 128.52,64.96 129.22,64.26 S1.B3
200V_  (via drill 0.81)
  Top 0.406: IC6.10 125.79,30.8 125.79,32.58 124.21,32.58 v122.62,34.29 | SL3.6 120.84,82.55 109.98,72.26 109.98,60.71 v110.05,60.45 | v110.05,51.56 110.62,50.93 111.25,50.29 118.05,43.56 v118.05,34.35
  Bottom 0.406: v110.05,60.45 v110.05,51.56 | v118.05,34.35 v122.62,34.29
200VXOR  (via drill 0.81)
  Top 0.406: 127.67,33.25 127.64,33.21 | 127.67,33.25 IC6.8 | v119.7,48.54 121.98,46.25 121.98,37.91 127.7,37.91 | 127.7,37.91 127.7,33.27 127.67,33.25 | 127.7,37.91 R29.2
  Bottom 0.406: S1.C3 119.7,58.55 119.7,57.55 121.14,56.11 121.14,52.45 119.69,51 v119.7,48.54
A1
  Bottom 0.406: DIS1.21 32.96,76.77 32.96,80.58 58.36,80.58 58.36,66.61 IC8.5
A2
  Bottom 0.406: DIS1.25 6.92,66.61 6.92,82.49 27.24,82.49 27.24,85.66 63.44,85.66 63.44,48.83 IC8.12
A3
  Bottom 0.406: IC8.23 26.42,33.59 26.42,47.18 17.72,47.18 17.72,53.91 DIS1.30
AB4
  Top 0.406: DIS1.7 49.47,43.75 49.47,31.05 IC8.19
  Bottom 0.406: IC8.19 51.05,31.05 51.05,24.07 9.46,24.07 9.46,43.81 13.91,43.81 DIS1.34 DIS1.35
B1
  Top 0.406: IC8.4 51.37,69.15 50.1,70.42 50.1,76.14 49.47,76.77 DIS1.20
B2
  Bottom 0.406: DIS1.24 8.19,69.15 8.19,81.22 28.51,81.22 28.51,84.39 62.17,84.39 62.17,51.37 IC8.11
B3  (via drill 0.81)
  Top 0.406: v57.34,20.7 v48.2,20.7
  Bottom 0.406: DIS1.29 6.92,56.45 6.98,20.7 v48.2,20.7 | v57.34,20.7 58.04,20.7 59.63,22.23 59.63,38.67 IC8.16
BP  (via drill 0.81)
  Top 0.406: v46.93,25.97 46.93,24.7 45.02,22.8 45.02,19.81 45.91,18.92 58.1,18.92 61.34,22.16 SL1.6 63.56,22.16 | DIS1.5 44.26,38.67 44.26,28.51 DIS1.1
  Bottom 0.406: IC8.21 DIS1.1 v46.93,25.97 13.91,25.97 DIS1.40 14.03,28.51 | DIS1.36 13.97,38.67 13.97,36.13 DIS1.37 11.11,36.13 11.11,28.51 14.03,28.51 | DIS1.6 46.8,41.21 46.8,38.67 DIS1.5 | 14.03,28.51 14.03,28.45
BPXOR  (via drill 0.81)
  Top 0.406: IC6.6 133.82,32.13 136.08,32.13 138.24,34.29 144.08,34.29 145.16,33.21 145.16,27.81 142.24,27.81 138.62,24.19 136.08,24.19 136.08,26.99 IC6.2 130.05,26.99 | 130.05,26.99 IC6.13 | IC6.9 129.29,32.07 130.05,31.3 130.05,26.99 | SL4.6 105.73,78.17 101.92,74.36 v101.92,63.25 | v101.92,48.2 113.92,36.13 113.92,25.59 115.7,23.81 129.79,23.81 130.05,24.07 130.05,26.99
  Bottom 0.406: v101.92,63.25 v101.92,48.2
C1
  Bottom 0.406: DIS1.19 50.1,74.23 50.1,78.68 57.09,78.68 57.09,71.69 IC8.3
C2
  Bottom 0.406: IC8.10 50.74,53.91 50.74,64.07 DIS1.15
C3
  Bottom 0.406: IC8.24 41.85,36.13 41.85,53.91 DIS1.11
CLIP  (via drill 0.81)
  Top 0.406: SL2.4 59.63,29.78 56.45,26.61 v49.53,26.61 | v18.29,29.78 18.29,58.99 DIS1.28
  Bottom 0.406: v49.53,26.61 49.53,29.78 v18.29,29.78
CLIP1  (via drill 0.81)
  Top 0.406: IC9.7 160.59,40.7 160.21,41.09 156.53,41.09 155.77,41.15 155.55,41.12 R36.2 155.45,27.61 | 155.45,27.61 155.45,21.97 155.51,21.97 155.51,18.16 v124.52,18.16 | IC6.12 127.67,28.32 124.59,28.32 v124.59,27.37 | 155.45,27.61 155.44,27.61 155.44,27.62 R48.1
  Bottom 0.406: v124.52,18.16 v124.59,27.37 123.57,27.37 123.57,27.43 122.68,28.32 R28.2 121.75,28.26
CLIP_  (via drill 0.81)
  Top 0.406: IC6.11 126.49,29.53 126.11,29.91 124.21,29.91 v122.55,31.56 | v115.89,31.69 115.89,36.83 103.25,49.47 v103.25,51.56 | v103.25,60.33 103.25,73.34 113.22,83.31 SL3.3
  Bottom 0.406: v122.55,31.56 122.55,31.62 v115.89,31.69 | v103.25,60.33 v103.25,51.56
D1
  Bottom 0.406: DIS1.18 52.01,71.69 52.01,74.23 IC8.2
D2
  Top 0.406: DIS1.14 48.83,61.53 50.74,59.63 50.74,57.72 52.01,56.45 IC8.9
D3
  Bottom 0.406: DIS1.10 50.74,51.37 50.74,41.21 IC8.15
DIG_GND
  Top 0.406: IC8.37 43.12,69.15 43.05,24.77 41.59,24.77 41.59,15.88 59.56,15.88 60.52,17.08 SL1.4
DIGGND  (via drill 0.81)
  Top 0.406: R29.1 134.39,35.5 133.79,35.5 133.79,33.34 IC6.7 | IC6.7 133.86,33.34 | IC6.7 135.95,33.34 137.99,35.37 144.78,35.37 146.49,33.66 146.49,31.75 146.56,31.69 R30.1 R31.1 | R31.1 146.62,25.65 | v118.91,22.1 v129.1,22.1 | 146.52,25.46 146.56,25.46 | 146.52,25.46 R31.1 | v146.43,22.1 146.43,25.46 146.52,25.46 | v111.95,28.32 111.95,35.62 105.09,42.04 v100.71,46.36 | 100.65,94.3 SL4.4 100.65,77.28 v100.46,76.14
  Bottom 0.406: v129.1,22.1 v146.43,22.1 | 118.91,28.19 R28.1 v111.95,28.32 | 118.91,28.19 v118.91,22.1 | 118.91,28.19 118.87,28.19 | v100.71,46.36 100.46,46.61 v100.46,76.14
E1
  Bottom 0.406: IC8.8 52.01,58.99 52.01,69.15 DIS1.17
E2
  Bottom 0.406: IC8.14 52.01,43.75 52.01,52.64 49.47,52.64 49.47,58.99 DIS1.13
E3
  Bottom 0.406: IC8.18 49.47,33.59 49.47,48.83 DIS1.9
F1
  Bottom 0.406: DIS1.22 10.73,74.23 10.73,78.68 31.05,78.68 31.05,81.85 59.63,81.85 59.63,64.07 IC8.6
F2
  Bottom 0.406: DIS1.26 1.79,64.07 1.79,83.76 25.97,83.76 25.97,86.93 64.71,86.93 64.71,46.29 IC8.13
F3  (via drill 0.81)
  Top 0.406: v55.75,22.35 v50.1,22.35
  Bottom 0.406: DIS1.31 8.19,51.37 8.19,22.35 v50.1,22.35 | v55.75,22.35 56.9,23.3 56.9,36.07 IC8.17
G1
  Bottom 0.406: DIS1.23 9.46,71.69 9.46,79.95 29.78,79.95 29.78,83.12 60.9,83.12 60.9,61.53 IC8.7
G2
  Bottom 0.406: IC8.25 27.88,38.67 27.88,49.02 19.62,49.02 19.62,61.53 DIS1.27
G3
  Bottom 0.406: IC8.22 25.08,31.05 25.08,45.4 16.45,45.4 16.45,48.83 DIS1.32
GND  (via drill 0.81)
  Top 0.406: IC8.26 36.13,41.21 v36.13,13.97 | v45.02,13.97 60.52,13.97 61.09,14.54 SL1.3
  Bottom 0.406: v36.13,13.97 v45.02,13.97
GNDA  (via drill 0.81)
  Top 0.406: IC1.IN1 138.56,72.64 137.86,73.34 | 137.86,73.34 IC1.OUT_RTN 133.67,73.34 v133.67,76.14 | 138.56,74.04 IC1.NC | 138.56,74.04 137.86,73.34 | 138.56,74.04 138.56,79.18 138.53,79.21 R26.1 138.56,79.25 138.62,79.18 138.68,79.25 v138.68,83 | IC2.6 93.15,81.98 93.15,81.91 | v127.57,76.14 123.19,76.14 v123.19,74.23
  Top 0.813: PAD6.1 125.22,94.68 124.4,93.66 123.7,92.84 v123.7,87.44 | 93.15,81.91 90.11,81.91 90.11,84.52 IC2.2 85.57,84.54 80.73,84.54 79.84,83.36 79.84,58.07 v82.54,55.37 | C7.1 147.46,83.99 148.53,85.06 148.53,86.01 148.49,86.01 IC5.3
  Bottom 0.406: 123.13,70.74 S1.A4 | 123.13,70.74 123.19,70.67 | 123.19,70.67 123.19,64.52 124.02,63.63 127.13,63.63 127.83,62.93 128.65,60.9 S1.B4 | C5.1 133.16,86.23 | 128.59,86.23 128.65,86.17 | IC5.3 148.53,85.92 | SL4.2 95.57,96.33 | v133.67,76.14 v127.57,76.14 | 123.13,70.74 123.13,70.67 123.19,70.67 | v123.19,74.23 123.13,74.23 123.13,70.74 | 138.69,83.04 138.68,83.03 v138.68,83 | 141.37,82.51 R49.1
  Bottom 0.813: 133.16,86.23 C4.1 | 128.65,86.17 C5.1 | v123.7,87.44 124.84,86.23 128.46,86.23 | C4.1 v138.68,83 | C4.1 138.68,87.76 139.83,88.9 147.51,88.9 148.46,87.95 IC5.3 | 95.57,96.33 94.93,96.97 83.57,96.97 82.36,95.76 82.36,85.47 83.28,84.55 | 83.28,84.55 83.31,84.52 | SL4.2 95.57,96.52 99.57,102.74 125.22,102.74 PAD6.1 | 138.69,83.04 139.22,82.51 141.37,82.51 | 83.28,84.55 83.26,84.54 83.28,84.52 IC2.2 | 83.28,84.55 | U$2.PAD 152.34,10.9 149.91,13.33 102.55,13.33 99.14,16.74 | 99.14,16.74 89.11,16.74 86.51,19.34 86.51,28.87 82.54,32.84 v82.54,55.37 82.54,55.44 | R23.1 100.63,20.83 99.18,19.38 | 99.18,19.38 99.07,19.27 99.07,17.03 99.14,16.96 99.14,16.74 | R2.1 98.33,22.61 98.78,22.16 98.78,19.77 99.18,19.38 | 99.18,19.38 99.22,19.34
  Bottom 1.016: 128.59,86.23 C6.1 128.46,86.23
LED+  (via drill 0.81)
  Top 0.406: SL2.6 59.63,24.7 58.36,23.94 v54.17,23.94 | v13.27,9.46 13.27,18.35 4.38,18.35 U$3.A 1.84,32.96 1.84,69.79 U$5.A
  Bottom 0.406: v54.17,23.94 54.17,9.46 36.77,9.46 34.23,12.64 32.32,15.18 27.88,15.18 22.16,9.46 v13.27,9.46
LED+1
  Bottom 0.813: R47.2 154.56,97.54 152.97,99.12 108.14,99.25 SL3.1
LED-  (via drill 0.81)
  Top 0.406: SL2.5 59.63,27.24 56.96,25.27 v52.51,25.27 | v15.81,12.64 15.81,20.7 6.92,20.7 6.92,35.5 U$3.K 4.38,54.55 6.92,54.55 6.92,72.33 U$5.K
  Bottom 0.406: v52.51,25.27 52.51,15.94 38.35,15.94 37.08,17.21 27.11,17.21 25.65,16.07 21.53,12.64 v15.81,12.64
LED-1
  Bottom 0.406: IC7.5 157.1,90.61 158.24,91.76 C24.-
  Bottom 0.813: SL3.2 110.68,97.28 152.97,96.84 152.97,94.17 C24.-
N$1
  Top 0.406: 10.22,92.46 10.22,97.79 65.98,97.79 65.98,6.98 10.22,6.98 10.22,12.32
N$2
  Top 0.406: 6.67,88.84 0,88.84 0,15.94 6.67,15.94
N$3  (via drill 0.81)
  Top 0.406: v114.17,57.21 95.19,57.21 95.19,41.85 82.17,41.85 82.17,38.04 83.76,36.45 v85.28,36.45
  Bottom 0.406: S1.A 116.01,66.23 114.3,66.23 114.17,66.17 v114.17,57.21 | v85.28,36.45 R3.2
N$4
  Top 0.813: R5.1 96.42,36.2 91.86,36.2 R4.1
N$5
  Top 0.813: R7.2 101.47,38.99 96.55,38.99 R5.2
N$6
  Top 0.813: R8.1 101.54,30.51 101.54,36.17 R7.1
N$7
  Top 0.813: 96.23,27.5 96.2,27.5 | 96.23,27.5 R9.2 | R8.2 101.37,27.5 96.23,27.5
N$8
  Top 0.813: R10.1 91.25,30.35 96.24,30.35 R9.1
N$9
  Top 0.406: IC8.34 36.13,61.53 C19.2
N$10
  Top 0.813: R10.2 R11.2
N$11
  Top 0.813: R11.1 91.31,18.71 91.31,18.61 96.1,18.61 R12.1
N$12
  Top 0.813: R13.2 101.66,21.53 96.35,21.53 R12.2
N$13
  Top 0.813: R14.1 103.31,14.95 103.31,17.12 R13.1
N$14  (via drill 0.81)
  Top 0.813: R14.2 v103.25,8.13
  Bottom 0.406: U$1.PAD 93.85,7.87 94.11,8.13
  Bottom 1.016: v103.25,8.13 94.11,8.13
N$15
  Bottom 0.406: S1.A1 115.44,64.26 115.44,58.54 115.97,58.02 115.97,46.45 130.24,46.45 130.26,51.72 130.26,55.8 133.66,59.2 133.66,64.47 134.74,65.55 136.54,65.55 136.54,72.29 126.3,72.29 S1.B1
N$16
  Top 0.406: R22.2 86.58,74.45 85.47,73.34 | 85.47,71.63 R21.1 | 85.47,73.34 85.47,71.63 | 85.47,71.63 85.53,71.56 | 85.47,73.34 84.33,74.49 82.3,74.49 81.28,75.88 81.28,80.07 83.18,81.98 IC2.3
  Bottom 0.406: IC2.3 83.18,81.98 81.28,80.07 81.28,76.26 | 81.28,76.26 C3.+ | 81.28,76.26 81.22,76.2
N$17
  Top 0.406: R27.1 156.2,52.9 156.2,56.15 157.39,57.34 164.51,57.28 164.5,71 151.43,71 150.73,71.76 150.73,73.52 149.48,73.52 R25.1 148.97,73.4 141.43,73.4 | 141.43,79.25 141.43,79.26 | 141.43,79.25 R26.2 | IC1.IN2 141.43,73.34 141.43,73.4 | 141.43,73.4 141.43,74.09 | 141.43,74.09 141.43,79.25 | 141.43,74.09 141.44,74.08
N$18  (via drill 0.81)
  Top 0.406: v138.49,68.16 v134.7,68.16
  Bottom 0.406: S1.B 128.92,70.05 131.46,70.05 133.36,68.16 v134.7,68.16 | v138.49,68.16 141.63,71.29 141.63,74.25 142.15,74.76 142.81,74.76 144.05,76 144.01,76.04 PAD8.1 143.91,76.03 | 143.91,76.03 143.9,76.03 | C8.1 143.91,76.03
N$19
  Bottom 0.406: C23.+ 163.39,79.38
  Bottom 0.813: IC7.2 163.39,85.53 162.05,84.2 162.05,80.71 163.39,79.38
N$20
  Top 0.406: R3.3 87.82,38.99 87.88,38.93 88.04,39.08 | R3.1 87.88,33.97 87.82,34.04
  Top 1.016: R4.2 88.04,39.08 | R3.3 87.82,34.04
N$21
  Bottom 0.406: PAD3.1 97.92,69.72 97.85,69.66 PAD2.1
N$22
  Bottom 0.406: R16.2 94.91,31.14 94.84,31.2 R15.1
N$23
  Bottom 0.406: R19.2 104.61,31.28 104.58,31.3 104.61,31.33 R18.1
N$24
  Bottom 0.406: 97.75,27.08 R17.2 | R16.1 97.75,27.08 | 97.75,27.08 97.73,27.05
N$25
  Bottom 0.406: R20.2 101.77,26.57 101.73,26.61 101.77,26.65 R19.1
N$26
  Bottom 0.406: R17.1 92.58,27.18 91.06,25.65 91.06,22.48 91.88,21.65 R2.2 93.79,21.65 94.68,20.77 R2.3
N$27
  Top 0.406: R25.2 147.75,70.69 146.44,69.38 146.44,67.32 IC3.2
  Bottom 0.406: IC3.2 146.43,64.64 143.89,62.1 143.91,62.09 143.91,59.67 | 143.91,59.67 143.91,59.63 | 143.91,59.67 IC3.6
N$28
  Bottom 0.406: 104.14,22.67 R23.3 | 104.14,22.67 104.84,21.97 105.79,21.97 106.05,21.72 R23.2 | R20.1 104.61,23.96 104.58,23.94 104.58,23.05 104.14,22.61 104.14,22.67
N$29
  Top 0.406: IC2.5 93.22,78.11 R1.3
N$30
  Top 0.406: IC2.1 85.6,90.11 95.95,90.11 R1.1
N$31
  Top 0.406: 142.88,53.78 R24.E 141.35,55.31 IC3.5
N$32
  Top 0.406: IC3.1 151.18,67.29 152.34,68.52 152.34,69.83 163.22,69.82 163.22,58.65 156.17,58.6 154.88,57.3 154.88,53.86 149.99,53.85 R24.A
N$33
  Bottom 0.406: IC3.3 143.89,69.4 143.3,69.99 143.3,72.12 144.05,72.87 149.74,72.87 | 149.74,72.87 149.75,72.87 | 144.73,79.69 R49.2 | 144.73,79.69 144.77,79.69 | 144.73,79.69 146.31,79.69 C8.2 147.2,78.85 149.78,78.85 150.17,78.46 PAD7.1 150.17,73.29 149.74,72.86 149.74,72.87
N$34
  Top 0.406: IC9.3 159.32,47.69 158.75,48.26 R35.2 157.51,48.22 157.42,48.13 157.42,46.61 155.47,45.05 R36.1
N$35
  Bottom 0.813: IC7.4 161,90.61 159.86,89.47 159.86,81.08 158.37,79.5 C23.-
N$36
  Top 0.406: R32.1 R33.2
N$37
  Top 0.406: 137.6,98.42 137.25,98.02 R33.1 | 137.6,98.42 C10.1 | C10.1 141.86,98.11 C10.1 | C10.1 C11.1 | C10.1 | 137.6,98.42 PAD5.1
N$38
  Bottom 0: 82.74,9.65 82.74,7.62
N$39
  Top 0.406: IC1.VOUT 135.7,82.23 134.3,83.63 126.11,83.63 126.11,91.25 C6.2 128.52,96.2 R32.2
  Bottom 0.406: C6.2 C5.2 138.62,91.25 C4.2
N$40
  Top 0.406: R27.2 160.65,52.9 160.59,52.83 IC9.2
N$41
  Top 0.406: R34.2 148.42,98.46 148.4,98.49 146.3,98.49 C10.2 144.66,97.73 144.65,97.73 144.65,96.71 144.08,96.14 140.91,96.14 140.91,90.55 142.62,89.09 145.22,89.09 145.92,88.39 IC5.2
N$42
  Top 0.406: C11.2 146.18,101.73 146.56,101.35 148.27,101.35 148.34,101.28 148.36,101.31 R34.1 149.77,101.31 150.62,100.46 150.62,97.03 149.8,96.2 149.1,96.2 148.46,95.57 IC5.6
N$43
  Bottom 0: 83.82,8.64 81.72,8.64
N$44
  Bottom 0: 162.24,66.93 162.24,68.96
N$45
  Bottom 0: 161.23,67.94 163.32,67.94
N$46
  Top 0: 162.24,66.93 162.24,68.96
N$47
  Top 0: 161.23,67.94 163.32,67.94
N$48
  Top 0.406: IC9.5 158.05,37.53 157.8,37.27 R45.3
N$49
  Top 0.406: IC9.6 159.32,37.53 159.64,37.21 R45.1
N$50
  Top 0.406: R46.1 162.94,31.24 162.12,30.42 159.45,30.42 158.69,31.18 R45.2 158.69,32.38
N$51
  Top 0: 82.74,9.65 82.74,7.62
N$52
  Bottom 0.406: 168.02,104.97 168.08,104.97 | 168.02,104.97 78.17,104.97 78.17,25.34 | 168.02,104.97 167.96,104.9 167.96,25.34 162.88,25.34
N$53
  Bottom 0.406: 83.44,25.34 78.23,25.34
N$54
  Bottom 0.406: 83.38,17.34 78.3,17.34
N$55
  Bottom 0.406: 78.23,17.34 78.23,-0.19 167.96,-0.19 167.96,17.34 162.88,17.34
N$56
  Top 0: 83.82,8.64 81.72,8.64
N$57
  Top 0: 59.25,94.04 59.25,92.01
N$58
  Bottom 0.406: R38.2 25.34,60.9 25.18,61.05 R37.1 25.34,64.07 25.18,64.22 R40.2 25.18,68.36 26.61,69.79 D2.+
N$59
  Bottom 0.406: IC8.36 R42.2
N$60
  Bottom 0.406: R38.1 27.88,60.9 28.38,60.39 R6.1
N$61
  Bottom 0.406: R40.1 27.88,67.25 28.13,67.5 28.13,68.52 32.32,68.52 32.32,67.25 32.45,67.25 R42.3
N$62
  Bottom 0.406: R6.3 26.86,54.93 26.61,55.18 26.61,57.72 25.97,58.36 23.43,58.36 22.8,58.99 22.8,68.52 23.43,69.15 R39.2
N$63
  Bottom 0.406: R41.2 20.26,69.15 20.89,69.15 20.89,50.74 24.7,50.74 25.97,52.01 31.05,52.01 31.05,58.99 32.96,60.26 32.96,63.44 32.32,64.07 32.45,65.47 R42.1
N$64
  Top 0.406: IC8.33 36.13,58.99 C19.1
N$65
  Top 0.406: IC8.31 36.77,53.91 34.86,52.01 LSP5.MP
N$66
  Bottom 0.406: 10.22,92.46 10.22,97.79 65.98,97.79 65.98,6.98 10.22,6.98 10.22,12.32
N$67
  Top 0.406: IC8.29 C21.2
N$68
  Top 0.406: IC8.28 R43.2
N$69
  Bottom 0.406: 6.67,88.84 0,88.84 0,15.94 6.67,15.94
N$70
  Top 0.406: C20.2 29.78,45.66 30.42,46.29 | 31.69,46.29 R43.1 30.42,46.29 | C21.1 29.78,46.93 30.42,46.29
N$71
  Top 0.406: IC8.27 C20.1
N$72
  Top 0.406: C22.2 31.69,71.06 35.5,71.06 Q1.1 IC8.38
N$73
  Top 0.406: IC8.40 39.31,80.58 31.53,80.58 R44.1 31.53,73.6 31.69,73.6 C22.1
N$74
  Top 0: 60.32,93.03 58.23,93.03
N$75
  Top 0.406: IC8.39 Q1.2 35.5,75.5 34.86,75.5 34.86,77.41 R44.2 34.23,77.41
N$76
  Top 0: 19.05,17.4 19.05,15.37
N$77
  Top 0: 20.13,16.38 18.03,16.38
N$78
  Bottom 0: 19.05,17.4 19.05,15.37
N$79
  Bottom 0: 20.13,16.38 18.03,16.38
N$80
  Bottom 0: 59.25,94.04 59.25,92.01
N$81
  Bottom 0: 60.32,93.03 58.23,93.03
N$82
  Top 0.406: 83.38,25.34 78.17,25.34
N$83
  Top 0.406: 83.31,17.34 78.23,17.34
N$84  (via drill 0.81)
  Top 0.813: v132.21,53.42 133.5,53.42 136.76,56.75 136.76,61.77 138.4,63.41 138.43,63.38 158.34,63.38 v158.36,63.45 | IC7.8 156.03,81.99 156.03,78.24 158.34,75.93 v158.34,73.88
  Route14 0.406: 132.19,53.44 v118.97,53.44
  Route14 0.813: v132.21,53.42 132.19,53.44
  Bottom 0.813: S1.C4 117.41,58.21 117.92,57.7 117.92,54.71 v118.97,53.44 | v158.34,73.88 | v158.34,73.88 158.39,73.88 158.39,63.47 v158.36,63.45
N$85
  Top 0.406: 162.88,17.34 167.89,17.34 167.89,-0.19 78.17,-0.19 78.17,17.34
N$86
  Top 0.406: 162.88,25.34 167.96,25.34 167.96,104.97 78.1,104.97 78.1,25.34
N$87
  Bottom 0.406: 15127.21,16871.57 -98952.82,87335.94
N$88  (3 unrouted)
  Top 0.406: 73829.99,208130.05 -41936.38,18543.76 | -6700.65,53699.42 -40258.83,-142590.44
  Bottom 0.406: 57052.8,209807.78 -41936.35,18543.77 | -6700.63,53699.44 -46969.69,-140912.69
N$89  (3 unrouted)
  Top 0.406: -26680.68,144309.37 -1514.8,53704.43 | -21727.02,53704.42 67192.17,85589.1
  Bottom 0.406: -73656.89,144309.39 -1514.8,53704.45 | -21727.03,53704.41 -192854.7,83911.38
VBATT  (via drill 0.81)
  Top 0.406: v58.99,9.46 SL1.1 | v60.9,43.75 60.9,76.77 IC8.1 54.55,80.58 52.01,83.12 26.61,83.12 23.43,79.95 23.43,64.07 25.34,62.17 v31.05,62.17
  Bottom 0.406: v60.9,43.75 60.9,21.78 58.99,19.88 v58.99,9.46 | R37.2 31.05,64.07 v31.05,62.17
VCC  (via drill 0.81)
  Top 0.406: IC6.14 120.46,25.72 120.01,26.35 119.94,44.43 116.54,47.84 116.54,49.81 116.58,51.05 116.57,51.05 | C15.1 164.53,39.05 161.93,39.05 161.93,39.06 IC9.8 161.86,36.22 R46.2 163.07,35.14 163.07,35.05 v165.8,35.05 165.77,35.05 165.74,35.03 165.8,34.97 165.8,30.43 162.99,27.62 R48.2
  Top 0.813: v126.24,48.45 124.87,50.65 124.41,51.04 116.57,51.05 116.52,54.42 v97.79,54.42 | v154.37,75.03 v154.37,80.32
  Route14 0.406: v145.29,48.45 129.44,48.45 128.84,48.41 v126.24,48.45
  Bottom 0.406: S1.C 126.24,52.59 v126.24,48.45 | 91.57,69.02 91.57,69.03 C1.1 | 93.28,84.58 IC2.7 | 91.5,84.58 91.44,84.58 | IC5.7 145.92,91.63 147.38,90.61 152.53,90.61 153.18,89.72 153.17,83.74 154.37,82.54 v154.37,80.32 | IC3.7 146.43,59.75 146.49,59.82 146.43,59.88 | 145.22,48.51 v145.29,48.45 165.8,48.45 v165.8,35.05
  Bottom 0.813: IC4.IN 89.92,64.07 91.57,65.72 | 91.57,65.72 91.57,69.02 | 91.57,65.72 93.41,63.88 PAD1.1 94.74,54.42 v97.79,54.42 | C1.1 91.57,76.51 89.92,78.17 89.92,83 91.5,84.58 93.28,84.58 | SL4.1 92.07,94.23 90.17,92.33 90.17,85.85 91.44,84.58 | v154.37,75.03 154.37,65.71 153.67,64.94 153.21,64.39 152.12,63.45 148.15,63.44 146.43,61.72 146.43,59.88 | IC3.7 146.43,57.47 145.22,56.26 145.22,48.51
VCC/2_+_50MV
  Top 0.406: LSP6.MP 35.5,55.18 36.77,56.45 IC8.32 41.85,56.45 | 41.85,56.45 41.85,64.07 IC8.35 36.77,64.07 33.59,67.25 29.78,67.25 28.51,68.52 D2.FB | 41.85,51.37 IC8.30 | 41.85,56.45 41.85,51.37 | 41.85,51.37 41.78,25.84 40.2,25.84 40.2,12 SL1.2
  Bottom 0.406: R41.1 20.26,73.6 23.43,73.6 R39.1 23.58,73.75 24.64,74.93 27.82,74.93 D2.- D2.FB
VCCIO  (via drill 0.81)
  Top 0.406: IC1.V+ 131.83,72.64 v131.83,81.28
  Top 0.813: R21.2 85.47,68.9 84.01,67.5 v84.01,64.07
  Route14 0.406: v103,86.8 103,91.44 v80.58,91.44
  Bottom 0.406: IC4.OUT v84.01,64.07 84.01,68.83 | 84.01,68.83 C2.1 | v131.83,81.28 103,81.28 v103,86.8 | v80.58,91.44 79.5,90.36 79.5,68.83 84.01,68.83
VSS  (via drill 0.81)
  Top 0.406: IC1.GND 140.02,71.06 | IC3.4 141.35,67.44 141.41,67.5 141.35,67.56 | IC1.GND IC1.N_ENABLE 130.3,71.94 | 141.77,71.94 IC1.GND | 86.49,64.26 v86.55,64.26 | 87.38,67.18 86.49,66.29 | R22.1 91.29,71.6 91.25,71.56 91.31,71.5 91.31,67.18 | 161.86,42.8 IC9.1 | 161.86,42.8 161.29,42.23 158.69,42.23 158.05,42.86 | 158.05,44.39 IC9.4 158.05,42.86 | C15.2 162.75,41.91 161.86,42.8 | R24.S 146.49,42.55 157.73,42.55 158.05,42.86 | 150.98,83.44
  Top 0.813: 140.02,71.06 141.35,69.72 141.35,67.56 | 141.77,71.94 141.96,71.97 143.86,71.94 v145.15,70.94 | 150.98,83.44 IC5.4 151,89.28 153.67,91.95 153.67,95.88 154.69,96.9 163.32,96.9 C24.+ | 86.49,66.29 86.49,64.26 | 87.38,67.18 91.31,67.18 94.74,67.18 PAD4.1 94.74,71.56 95,71.82 R1.2 97.16,73.09 97.66,73.6 97.66,90.87 98.11,91.31 SL4.3 | v152.38,73.53 152.42,79.1 152.43,79.85 152.41,81.35 152.41,82.01 150.98,83.44 | 130.3,71.94 v130.3,78.55 | C7.2 150.98,82.8 150.98,83.44
  Bottom 0.406: IC3.4 141.35,64.58 140.08,63.31 139.13,63.31 139.13,49.85 145.29,43.69 R24.S | C2.2 86.67,71.63 88.84,69.47 88.77,69.4 C1.2 88.77,67.69 88.2,67.12 87.38,67.12 86.49,66.23 86.49,64.33 v86.55,64.26 86.49,64.2 IC4.GND | C3.- 81.33,73.08 81.34,73.09 82.8,71.63 C2.2 | IC2.4 85.6,79.38 85.53,79.31 C2.2 | 164.53,88.07 164.46,88.14 | 164.53,88.07 IC7.3 | 164.59,88.01 164.53,88.07
  Bottom 0.813: v145.15,70.94 150.18,70.99 152.36,70.96 v152.38,73.53 | v130.3,78.55 97.66,78.55 97.66,90.87 98.11,91.31 SL4.3 | C24.+ 165.42,94.17 | 165.42,94.17 166.94,92.65 166.94,88.77 166.18,88.01 164.59,88.01 | R47.1 165.44,94.2 165.42,94.17
(copper drawn outside any net)
  shapes: Bottom circle x9, Top circle x6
